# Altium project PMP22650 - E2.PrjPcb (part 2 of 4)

## Sheet PMP22650 PFC GaN PH2.SchDoc
size 431 x 279 mm; DocumentNumber: 6; SheetNumber: 6; SheetTotal: 16; PageSetup: Record=PageOptions¦CenterHorizontal=True¦CenterVertical=True¦PrintScale=0.69¦XCorrection=1.00¦YCorrection=1.00¦PrintKind=0¦BorderSize=5000000¦LeftOffset=0¦BottomOffset=0¦Orientation=2¦PaperLength=1000¦PaperWidth=1000¦Scale=100¦PaperSource=15¦PrintQuality=600¦MediaType=1¦DitherType=10¦PaperKind=Letter¦PrintScaleMode=1
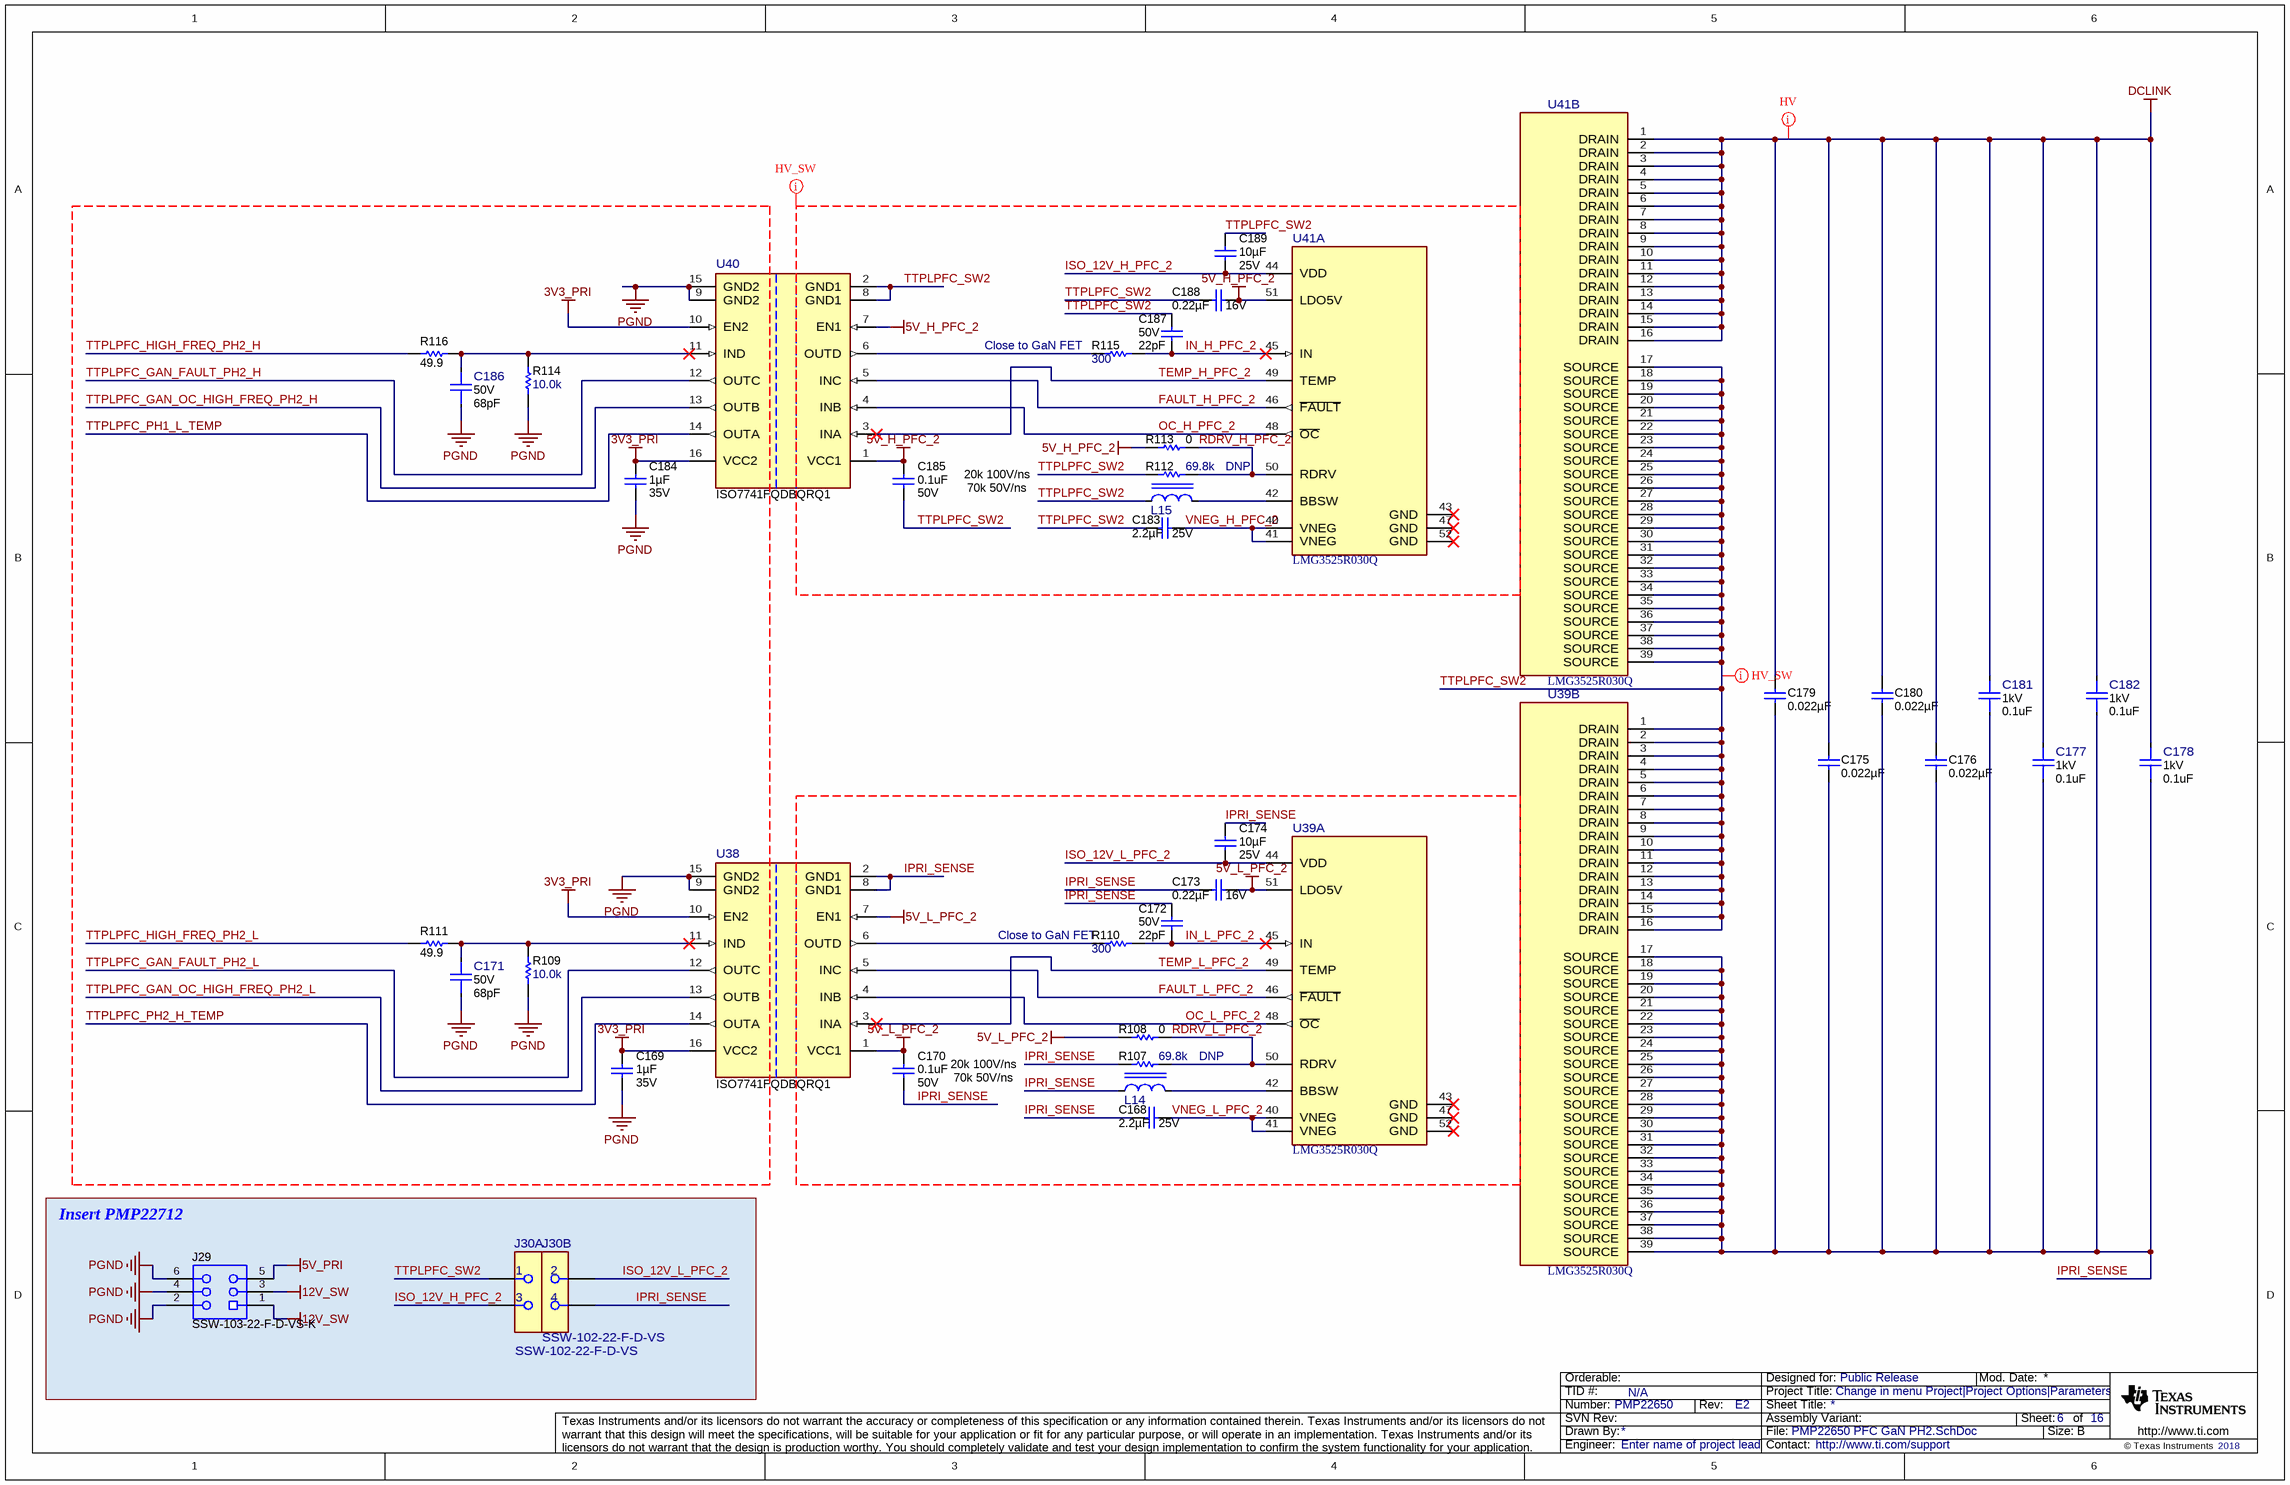
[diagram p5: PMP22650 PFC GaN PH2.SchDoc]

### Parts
C168  Cap_F: 2.2µF  VDC_V: 25V  [0805_HV]  (hidden comment: CGA4J3X7R1E225K125AB)
C169  VDC_V: 35V  ValueDisplayed: 1µF  [0402]  (hidden comment: GRT155R6YA105KE13D)
C170  VDC_V: 50V  ValueDisplayed: 0.1uF  [0402]  (hidden comment: GCM155R71H104KE02D)
C171  VDC_V: 50V  ValueDisplayed: 68pF  [FP-GCM1555C1H680JA16D_0402-MFG]  (hidden comment: GCM1555C1H680JA16D)
C172  VDC_V: 50V  ValueDisplayed: 22pF  [0402]  (hidden comment: GCM1555C1H220JA16D)
C173  VDC_V: 16V  ValueDisplayed: 0.22µF  [0402]  (hidden comment: GCM155R71C224KE02D)
C174  VDC_V: 25V  ValueDisplayed: 10µF  [1206_180]  (hidden comment: TMK316AB7106KLHT)
C175  ValueDisplayed: 0.022µF  [1206_190]  (hidden comment: C1206C223KDRACTU)
C176  ValueDisplayed: 0.022µF  [1206_190]  (hidden comment: C1206C223KDRACTU)
C177  VDC_V: 1kV  ValueDisplayed: 0.1uF  [FP-C1812X104KDRACAUTO_1812-MFG]  (hidden comment: C1812X104KDRACAUTO)
C178  VDC_V: 1kV  ValueDisplayed: 0.1uF  [FP-C1812X104KDRACAUTO_1812-MFG]  (hidden comment: C1812X104KDRACAUTO)
C179  ValueDisplayed: 0.022µF  [1206_190]  (hidden comment: C1206C223KDRACTU)
C180  ValueDisplayed: 0.022µF  [1206_190]  (hidden comment: C1206C223KDRACTU)
C181  VDC_V: 1kV  ValueDisplayed: 0.1uF  [FP-C1812X104KDRACAUTO_1812-MFG]  (hidden comment: C1812X104KDRACAUTO)
C182  VDC_V: 1kV  ValueDisplayed: 0.1uF  [FP-C1812X104KDRACAUTO_1812-MFG]  (hidden comment: C1812X104KDRACAUTO)
C183  Cap_F: 2.2µF  VDC_V: 25V  [0805_HV]  (hidden comment: CGA4J3X7R1E225K125AB)
C184  VDC_V: 35V  ValueDisplayed: 1µF  [0402]  (hidden comment: GRT155R6YA105KE13D)
C185  VDC_V: 50V  ValueDisplayed: 0.1uF  [0402]  (hidden comment: GCM155R71H104KE02D)
C186  VDC_V: 50V  ValueDisplayed: 68pF  [FP-GCM1555C1H680JA16D_0402-MFG]  (hidden comment: GCM1555C1H680JA16D)
C187  VDC_V: 50V  ValueDisplayed: 22pF  [0402]  (hidden comment: GCM1555C1H220JA16D)
C188  VDC_V: 16V  ValueDisplayed: 0.22µF  [0402]  (hidden comment: GCM155R71C224KE02D)
C189  VDC_V: 25V  ValueDisplayed: 10µF  [1206_180]  (hidden comment: TMK316AB7106KLHT)
J29  SSW-103-22-F-D-VS-K  [SAMTEC_SSW-103-22-F-D-VS-K]
J30  SSW-102-22-F-D-VS  [FP-SSW-102-22-F-D-VS_RCPT4-MFG]  (parts A,B of 2)
L14  MPIA2510V2-4R7-R  [FP-MPIA2510V2-4R7-R_1008-MFG]  (value not drawn)
L15  MPIA2510V2-4R7-R  [FP-MPIA2510V2-4R7-R_1008-MFG]  (value not drawn)
R107  ValueDisplayed: 69.8k  [0402]  (hidden comment: CRCW040269K8FKED)
R108  ValueDisplayed: 0  [0402]  (hidden comment: ERJ-2GE0R00X)
R109  ValueDisplayed: 10.0k  [0402]  (hidden comment: CRCW040210K0FKED)
R110  ValueDisplayed: 300  [0402]  (hidden comment: CRCW0402300RJNED)
R111  ValueDisplayed: 49.9  [0402]  (hidden comment: CRCW040249R9FKED)
R112  ValueDisplayed: 69.8k  [0402]  (hidden comment: CRCW040269K8FKED)
R113  ValueDisplayed: 0  [0402]  (hidden comment: ERJ-2GE0R00X)
R114  ValueDisplayed: 10.0k  [0402]  (hidden comment: CRCW040210K0FKED)
R115  ValueDisplayed: 300  [0402]  (hidden comment: CRCW0402300RJNED)
R116  ValueDisplayed: 49.9  [0402]  (hidden comment: CRCW040249R9FKED)
U38  ISO7741FQDBQRQ1  [DBQ0016A-MFG]
U39  LMG3525R030Q  [RQS0052A-MFG]  (parts A,B of 2)
U40  ISO7741FQDBQRQ1  [DBQ0016A-MFG]
U41  LMG3525R030Q  [RQS0052A-MFG]  (parts A,B of 2)

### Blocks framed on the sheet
Insert PMP22712: J29 J30

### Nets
3V3_PRI: C169.1 C184.1 U38.10(EN2) U38.16(VCC2) U40.10(EN2) U40.16(VCC2)
5V_H_PFC_2: C185.1 C188.1 R113.2 U40.1(VCC1) U40.7(EN1) U41.51(LDO5V)
5V_L_PFC_2: C170.1 C173.1 R108.2 U38.1(VCC1) U38.7(EN1) U39.51(LDO5V)
5V_PRI: J29.5
12V_SW: J29.1 J29.3
DCLINK: C175.1 C176.1 C177.2 C178.2 C179.1 C180.1 C181.2 C182.2 U41.1(DRAIN) U41.2(DRAIN) U41.3(DRAIN) U41.4(DRAIN) U41.5(DRAIN) U41.6(DRAIN) U41.7(DRAIN) U41.8(DRAIN) U41.9(DRAIN) U41.10(DRAIN) U41.11(DRAIN) U41.12(DRAIN) U41.13(DRAIN) U41.14(DRAIN) U41.15(DRAIN) U41.16(DRAIN)
PGND: C169.2 C171.1 C184.2 C186.1 J29.2 J29.4 J29.6 R109.1 R114.1 U38.9(GND2) U38.15(GND2) U40.9(GND2) U40.15(GND2)
FAULT_H_PFC_2: U40.5(INC) U41.46(~{FAULT})
FAULT_L_PFC_2: U38.5(INC) U39.46(~{FAULT})
IN_H_PFC_2: C187.2 R115.2 U41.45(IN)
IN_L_PFC_2: C172.2 R110.2 U39.45(IN)
IPRI_SENSE: C168.1 C170.2 C172.1 C173.2 C174.2 C175.2 C176.2 C177.1 C178.1 C179.2 C180.2 C181.1 C182.1 J30.4 L14.1 R107.1 U38.2(GND1) U38.8(GND1) U39.17(SOURCE) U39.18(SOURCE) U39.19(SOURCE) U39.20(SOURCE) U39.21(SOURCE) U39.22(SOURCE) U39.23(SOURCE) U39.24(SOURCE) U39.25(SOURCE) U39.26(SOURCE) U39.27(SOURCE) U39.28(SOURCE) U39.29(SOURCE) U39.30(SOURCE) U39.31(SOURCE) U39.32(SOURCE) U39.33(SOURCE) U39.34(SOURCE) U39.35(SOURCE) U39.36(SOURCE) U39.37(SOURCE) U39.38(SOURCE) U39.39(SOURCE)
ISO_12V_H_PFC_2: C189.1 J30.3 U41.44(VDD)
ISO_12V_L_PFC_2: C174.1 J30.2 U39.44(VDD)
OC_H_PFC_2: U40.4(INB) U41.48(~{OC})
OC_L_PFC_2: U38.4(INB) U39.48(~{OC})
RDRV_H_PFC_2: R112.2 R113.1 U41.50(RDRV)
RDRV_L_PFC_2: R107.2 R108.1 U39.50(RDRV)
TEMP_H_PFC_2: U40.3(INA) U41.49(TEMP)
TEMP_L_PFC_2: U38.3(INA) U39.49(TEMP)
TTPLPFC_GAN_FAULT_PH2_H: U40.12(OUTC)
TTPLPFC_GAN_FAULT_PH2_L: U38.12(OUTC)
TTPLPFC_GAN_OC_HIGH_FREQ_PH2_H: U40.13(OUTB)
TTPLPFC_GAN_OC_HIGH_FREQ_PH2_L: U38.13(OUTB)
TTPLPFC_HIGH_FREQ_PH2_H: R116.1
TTPLPFC_HIGH_FREQ_PH2_L: R111.1
TTPLPFC_PH1_L_TEMP: U40.14(OUTA)
TTPLPFC_PH2_H_TEMP: U38.14(OUTA)
TTPLPFC_SW2: C183.1 C185.2 C187.1 C188.2 C189.2 J30.1 L15.1 R112.1 U39.1(DRAIN) U39.2(DRAIN) U39.3(DRAIN) U39.4(DRAIN) U39.5(DRAIN) U39.6(DRAIN) U39.7(DRAIN) U39.8(DRAIN) U39.9(DRAIN) U39.10(DRAIN) U39.11(DRAIN) U39.12(DRAIN) U39.13(DRAIN) U39.14(DRAIN) U39.15(DRAIN) U39.16(DRAIN) U40.2(GND1) U40.8(GND1) U41.17(SOURCE) U41.18(SOURCE) U41.19(SOURCE) U41.20(SOURCE) U41.21(SOURCE) U41.22(SOURCE) U41.23(SOURCE) U41.24(SOURCE) U41.25(SOURCE) U41.26(SOURCE) U41.27(SOURCE) U41.28(SOURCE) U41.29(SOURCE) U41.30(SOURCE) U41.31(SOURCE) U41.32(SOURCE) U41.33(SOURCE) U41.34(SOURCE) U41.35(SOURCE) U41.36(SOURCE) U41.37(SOURCE) U41.38(SOURCE) U41.39(SOURCE)
VNEG_H_PFC_2: C183.2 U41.40(VNEG) U41.41(VNEG)
VNEG_L_PFC_2: C168.2 U39.40(VNEG) U39.41(VNEG)
NetC171_2: C171.2 R109.2 R111.2 U38.11(IND)
NetC186_2: C186.2 R114.2 R116.2 U40.11(IND)
NetL14_2: L14.2 U39.42(BBSW)
NetL15_2: L15.2 U41.42(BBSW)
NetR110_1: R110.1 U38.6(OUTD)
NetR115_1: R115.1 U40.6(OUTD)

Not connected (* = marked no-connect by the designer): U39 43(GND)* 47(GND)* 52(GND)*; U41 43(GND)* 47(GND)* 52(GND)*

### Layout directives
net class HV_SW: 5V_H_PFC_2, FAULT_H_PFC_2, IN_H_PFC_2, ISO_12V_H_PFC_2, OC_H_PFC_2, RDRV_H_PFC_2, TEMP_H_PFC_2, TTPLPFC_SW2, VNEG_H_PFC_2
net class HV: DCLINK

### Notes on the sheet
- (near R115) Close to GaN FET
- 20k 100V/ns
- 70k 50V/ns
- DNP
- (near R110) Close to GaN FET
- (near C170) 20k 100V/ns
- (near C170) 70k 50V/ns

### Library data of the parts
C168 C183 = CMP-0007975-2: CAP, CERM, 2.2 uF, 25 V, +/- 10%, X7R, AEC-Q200 Grade 1, 0805; Manufacturer: TDK; TaMin_C: -55°C; Polarized: N; SizeAreaWB_mm2: 6.75; Value1: Unknown; U/M: EA; Value: 2.2uF; TaMax_C: 125°C; SizeZ_mm: 1.45; SizeX_mm: 2; SizeY_mm: 1.25; Cap_Case: 0805; SizeArea_mm2: 2.5; AEC Qualified: Y; AEC Grade: 1; AEC Category: Q200
C169 C184 = CMP-0750099-1: CAP, CERM, 1 µF, 35 V,+/- 10%, X5R, AEC-Q200 Grade 3, 0402; Manufacturer: MuRata; AEC Grade: 3; AEC Category: Q200; Value: 1uF; SizeArea_mm2: 0.5; SizeZ_mm: 0.6; AEC Qualified: Y; TaMin_C: -55°C; SizeX_mm: 1; U/M: EA; Polarized: N; TaMax_C: 85°C
C170 C185 = CMP-0006356-2: CAP, CERM, 0.1 uF, 50 V, +/- 10%, X7R, AEC-Q200 Grade 1, 0402; Manufacturer: MuRata; TaMin_C: -55°C; Polarized: N; SizeAreaWB_mm2: 3; Value1: Unknown; U/M: EA; Value: 0.1uF; TaMax_C: 125°C; SizeZ_mm: 0.6; SizeX_mm: 1; SizeY_mm: 0.5; AEC Qualified: Y; Cap_F: 100nF; AEC Category: Q200
C171 C186 = CMP-0090521-1: 68pF ±5% 50V Ceramic Capacitor C0G, NP0 0402 (1005 Metric); Manufacturer: Murata; AEC Qualified: Yes; AEC Grade: Grade 1; TempCo: 30ppm/°C; SizeZ_mm: 0.55mm
C172 C187 = CMP-0006348-2: CAP, CERM, 22 pF, 50 V, +/- 5%, C0G/NP0, AEC-Q200 Grade 1, 0402; Manufacturer: MuRata; TaMin_C: -55°C; Polarized: N; SizeAreaWB_mm2: 3; Value1: Unknown; U/M: EA; Value: 22pF; TaMax_C: 125°C; SizeZ_mm: 0.6; SizeX_mm: 1; SizeY_mm: 0.5; AEC Qualified: Y; AEC Category: Q200
C173 C188 = CMP-0078265-1: CAP, CERM, 0.22 µF, 16 V,+/- 10%, X7R, AEC-Q200 Grade 1, 0402; Manufacturer: MuRata; TaMin_C: -55°C; Polarized: N; SizeAreaWB_mm2: 3; U/M: EA; Value: 0.22uF; TaMax_C: 125°C; SizeZ_mm: 0.6; SizeX_mm: 1; SizeY_mm: 0.5; AEC Qualified: Y; Cap_F: 220nF; AEC Category: Q200
C174 C189 = CMP-0750154-1: CAP, CERM, 10 µF, 25 V,+/- 10%, X7R, AEC-Q200 Grade 1, 1206; Manufacturer: Taiyo Yuden; AEC Qualified: Y; SizeZ_mm: 1.8; TaMax_C: 125°C; TaMin_C: -55°C; Cap_Case: 1206; Polarized: N; AEC Grade: 1; SizeY_mm: 1.6; Value: 10uF; SizeX_mm: 3.2; SizeAreaWB_mm2: 10.92; AEC Category: Q200; U/M: EA; SizeArea_mm2: 5.12
C175 C176 C179 C180 = CMP-0084048-1: CAP, CERM, 0.022 µF, 1000 V,+/- 10%, X7R, AEC-Q200 Grade 1, 1206; Manufacturer: Kemet; Polarized: N; CompType: Capacitor; Value: 0.022uF; U/M: EA; Cap_F: 22nF; VDC_V: 1kV; Value2: 1000V; TaMin_C: -55°C; TaMax_C: 125°C; Cap_Case: 1206; SizeArea_mm2: 5.12; SizeAreaWB_mm2: 10.92; SizeX_mm: 3.2; SizeY_mm: 1.6; SizeZ_mm: 1.9; AEC Category: Q200; AEC Qualified: Y; AEC Grade: 1
C177 C178 C181 C182 = CMP-0090548-1: 0.1µF ±10% 1000V (1kV) Ceramic Capacitor X7R 1812 (4532 Metric); Manufacturer: Kemet; SizeZ_mm: 1.85mm; AEC Qualified: Yes; Cap_F: 100nF; TempCo: 15%; Value: 100nF; AEC Grade: Grade 1
J29 = CMP-0055666-1: Receptacle, 2.54mm, 3x2, Tin, SMT; Manufacturer: Samtec; CNHeader: FALSE; Current_A: 5.7A; Gender: Female; CompType: Socket Strip; Row_Count: 2; RowSpacing_mm: 2.54; ContactFinish: Gold; CT: TRUE; Cert_UL: Y
J30 = CMP-0090790-1: 4 Position Receptacle Connector  Surface Mount; Manufacturer: Samtec; DUT-Pitch_mm: 2.54mm; SizeZ_mm: 10.21mm; Current_A: 4.7A; ContactFinish: Gold,Nickel; Conn Gender: Female; Voltage_V: 655V; Is Female: yes; AEC Qualified: No; Row_Count: 2; Conn Orientation: Vertical; Standoff Height: 0.97mm
L14 L15 = CMP-0090507-1: 4.7µH Shielded Molded Inductor 1.22A 262mOhm Max 1008 (2520 Metric); Manufacturer: Eaton; Material: Metal Composite; Value: 4.7uH; Test Frequency: 1MHz; Isat: 1.8A; DCR_ohm: 0.262; AEC Grade: Grade 1; Tolerance_%: 20%; AEC Qualified: Yes; Self Resonant Frequency: 25MHz; SizeZ_mm: 1.05mm; Shrouded: true
R107 R112 = CMP-0026510-2: RES, 69.8 k, 1%, 0.063 W, AEC-Q200 Grade 0, 0402; Manufacturer: Vishay-Dale; Power_W: 63mW; TempCo: 100 ppm/C; Value_Code: 69k8; Value: 69.8k; EIA_Code: E96; SizeX_mm: 1; SizeY_mm: 0.5; SizeZ_mm: 0.6; Value2: 0.063W; AEC Qualified: Y; VDC_V: 50V; AEC Category: Q200; AEC Grade: 0
R108 R113 = CMP-0026992-3: RES, 0, 5%, 0.1 W, AEC-Q200 Grade 0, 0402; Manufacturer: Panasonic; Power_W: 100mW; TempCo: 600 ppm/C; Value_Code: 0000; Value: 0; EIA_Code: E24; SizeX_mm: 1; SizeY_mm: 0.5; SizeZ_mm: 0.6; Value2: 0.1W; AEC Qualified: Y; VDC_V: 50V; AEC Category: Q200; SizeAreaWB_mm2: 3
R109 R114 = CMP-0025958-3: RES, 10.0 k, 1%, 0.063 W, AEC-Q200 Grade 0, 0402; Manufacturer: Vishay-Dale; Power_W: 63mW; TempCo: 100 ppm/C; Value_Code: 10k0; Value: 10.0k; EIA_Code: E96; Res_ohm: 10k; SizeX_mm: 1; SizeY_mm: 0.5; SizeZ_mm: 0.6; Value2: 0.063W; AEC Qualified: Y; VDC_V: 50V; AEC Category: Q200; AEC Grade: 0
R110 R115 = CMP-0026902-3: RES, 300, 5%, 0.063 W, AEC-Q200 Grade 0, 0402; Manufacturer: Vishay-Dale; Power_W: 63mW; TempCo: 200 ppm/C; Value_Code: 300R; Value: 300; EIA_Code: E24; SizeX_mm: 1; SizeY_mm: 0.5; SizeZ_mm: 0.6; Value2: 0.063W; AEC Qualified: Y; VDC_V: 50V; AEC Category: Q200; AEC Grade: 0
R111 R116 = CMP-0026404-2: RES, 49.9, 1%, 0.063 W, AEC-Q200 Grade 0, 0402; Manufacturer: Vishay-Dale; Power_W: 63mW; TempCo: 100 ppm/C; Value_Code: 49R9; Value: 49.9; EIA_Code: E96; SizeX_mm: 1; SizeY_mm: 0.5; SizeZ_mm: 0.6; Value2: 0.063W; AEC Qualified: Y; VDC_V: 50V; AEC Category: Q200; AEC Grade: 0
U38 U40 = CMP-0090469-1: Manufacturer: Texas Instruments; TaMin_C: -40°C; TaMax_C: +125°C; TJmax_C: +150°C; AEC Grade: Grade 1; Min Supply Voltage: 2.25V; AEC Qualified: Yes; Max Supply Voltage: 5.5V; Standoff Height: 0.11mm; Nominal Supply Current: 1.5-18mA; SizeZ_mm: 1.75mm
U39 U41 = CMP-0089968-2: 650-V 30-mΩ GaN FET with Integrated Driver and Protection; Manufacturer: Texas Instruments; Output Voltage: 520V; Nominal Supply Current: 540uA; Min Supply Voltage: 7.5V; Standoff Height: 0mm; AEC Grade: Grade 1; Max Supply Voltage: 18V; Number Of Outputs: 1; AEC Qualified: Yes; TJmax_C: +125°C; SizeZ_mm: 1mm; AEC Category: Q200; CompType: IC

## Sheet PMP22650 PFC LF FET Gate Driver.SchDoc
size A4; Date: Not shown in title block; ApprovedBy: Not shown in title block; CheckedBy: Not shown in title block; Author: Not shown in title block; CompanyName: Not shown in title block; Engineer: Not shown in title block; Organization: Not shown in title block; Address1: Not shown in title block; Address2: Not shown in title block; Address3: Not shown in title block; Address4: Not shown in title block; DocumentNumber: 7; Revision: Use project parameter SCH_Rev; SheetNumber: 7; SheetTotal: 16; PageSetup: Record=PageOptions¦CenterHorizontal=True¦CenterVertical=True¦PrintScale=1.00¦XCorrection=1.00¦YCorrection=1.00¦PrintKind=0¦BorderSize=5000000¦LeftOffset=0¦BottomOffset=0¦Orientation=2¦PaperLength=1000¦PaperWidth=1000¦Scale=100¦PaperSource=15¦PrintQuality=600¦MediaType=1¦DitherType=10¦PaperKind=Letter¦PrintScaleMode=1
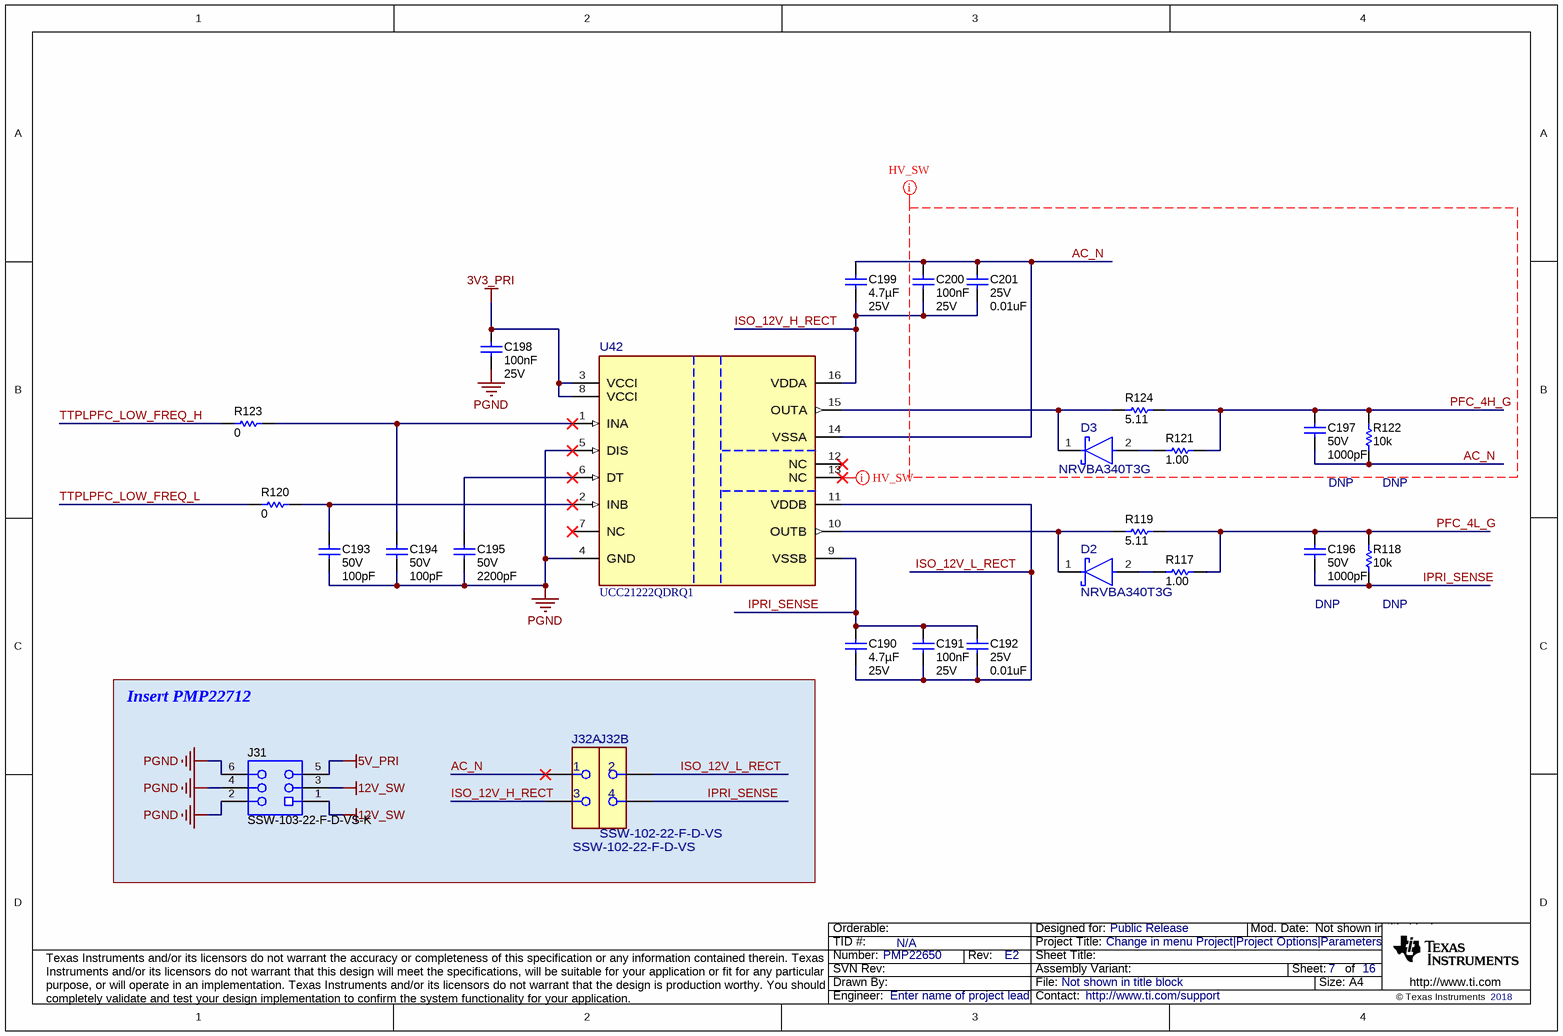
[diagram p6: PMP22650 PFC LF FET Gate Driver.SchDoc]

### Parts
C190  Cap_F: 4.7µF  VDC_V: 25V  [0805L]  (hidden comment: CGA4J1X7R1E475K125AC)
C191  Cap_F: 100nF  VDC_V: 25V  [0603]  (hidden comment: CGA3E2X7R1E104K080AA)
C192  VDC_V: 25V  ValueDisplayed: 0.01uF  [0603]  (hidden comment: C0603C103J3GECAUTO)
C193  VDC_V: 50V  ValueDisplayed: 100pF  [0603]  (hidden comment: CGA3E2NP01H101J080AA)
C194  VDC_V: 50V  ValueDisplayed: 100pF  [0603]  (hidden comment: CGA3E2NP01H101J080AA)
C195  VDC_V: 50V  ValueDisplayed: 2200pF  [0402]  (hidden comment: CGA2B2X7R1H222K050BA)
C196  VDC_V: 50V  ValueDisplayed: 1000pF  [0402]  (hidden comment: CGA2B2X7R1H102K050BA)
C197  VDC_V: 50V  ValueDisplayed: 1000pF  [0402]  (hidden comment: CGA2B2X7R1H102K050BA)
C198  Cap_F: 100nF  VDC_V: 25V  [0603]  (hidden comment: CGA3E2X7R1E104K080AA)
C199  Cap_F: 4.7µF  VDC_V: 25V  [0805L]  (hidden comment: CGA4J1X7R1E475K125AC)
C200  Cap_F: 100nF  VDC_V: 25V  [0603]  (hidden comment: CGA3E2X7R1E104K080AA)
C201  VDC_V: 25V  ValueDisplayed: 0.01uF  [0603]  (hidden comment: C0603C103J3GECAUTO)
D2  NRVBA340T3G  [FP-NRVBA340T3G_SMA-MFG]
D3  NRVBA340T3G  [FP-NRVBA340T3G_SMA-MFG]
J31  SSW-103-22-F-D-VS-K  [SAMTEC_SSW-103-22-F-D-VS-K]
J32  SSW-102-22-F-D-VS  [FP-SSW-102-22-F-D-VS_RCPT4-MFG]  (parts A,B of 2)
R117  ValueDisplayed: 1.00  [1206]  (hidden comment: CRCW12061R00FKEA)
R118  ValueDisplayed: 10k  [0603]  (hidden comment: CRCW060310K0JNEA)
R119  ValueDisplayed: 5.11  [1206]  (hidden comment: CRCW12065R11FKEA)
R120  ValueDisplayed: 0  [0402]  (hidden comment: RK73Z1ETTP)
R121  ValueDisplayed: 1.00  [1206]  (hidden comment: CRCW12061R00FKEA)
R122  ValueDisplayed: 10k  [0603]  (hidden comment: CRCW060310K0JNEA)
R123  ValueDisplayed: 0  [0402]  (hidden comment: RK73Z1ETTP)
R124  ValueDisplayed: 5.11  [1206]  (hidden comment: CRCW12065R11FKEA)
U42  UCC21222QDRQ1  [D0016B-MFG]

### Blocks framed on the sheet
Insert PMP22712: J31 J32

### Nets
3V3_PRI: C198.1 U42.3(VCCI) U42.8(VCCI)
5V_PRI: J31.5
12V_SW: J31.1 J31.3
PGND: C193.2 C194.2 C195.2 C198.2 J31.2 J31.4 J31.6 U42.4(GND) U42.5(DIS)
AC_N: C197.2 C199.1 C200.1 C201.1 J32.1 R122.1 U42.14(VSSA)
IPRI_SENSE: C190.1 C191.1 C192.1 C196.2 J32.4 R118.1 U42.9(VSSB)
ISO_12V_H_RECT: C199.2 C200.2 C201.2 J32.3 U42.16(VDDA)
ISO_12V_L_RECT: C190.2 C191.2 C192.2 J32.2 U42.11(VDDB)
PFC_4H_G: C197.1 R121.2 R122.2 R124.2
PFC_4L_G: C196.1 R117.2 R118.2 R119.2
TTPLPFC_LOW_FREQ_H: R123.1
TTPLPFC_LOW_FREQ_L: R120.1
NetC193_1: C193.1 R120.2 U42.2(INB)
NetC194_1: C194.1 R123.2 U42.1(INA)
NetC195_1: C195.1 U42.6(DT)
NetD2_1: D2.1(Cathode) R119.1 U42.10(OUTB)
NetD2_2: D2.2(Anode) R117.1
NetD3_1: D3.1(Cathode) R124.1 U42.15(OUTA)
NetD3_2: D3.2(Anode) R121.1

Not connected (* = marked no-connect by the designer): U42 7(NC)* 12(NC)* 13(NC)*

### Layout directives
net class HV: AC_N, NetU42_13, PFC_4H_G

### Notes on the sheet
- DNP
- (near R122) DNP
- (near R118) DNP

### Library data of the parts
C190 C199 = CMP-0076706-1: CAP, CERM, 4.7 µF, 25 V,+/- 10%, X7R, AEC-Q200 Grade 1, 0805; Manufacturer: TDK; SizeAreaWB_mm2: 6.75; SizeArea_mm2: 2.5; AEC Qualified: Y; AEC Category: Q200; Value: 4.7uF; TaMax_C: 125°C; SizeZ_mm: 1.45; AEC Grade: 1; Polarized: N; TaMin_C: -55°C; SizeY_mm: 1.25; U/M: EA; SizeX_mm: 2.0; Cap_Case: 2x1.25x1.25mm
C191 C198 C200 = CMP-0007077-5: CAP, CERM, 0.1 uF, 25 V, +/- 10%, X7R, AEC-Q200 Grade 1, 0603; Manufacturer: TDK; TaMin_C: -55°C; Polarized: N; SizeAreaWB_mm2: 4.68; Value1: Unknown; U/M: EA; Value: 0.1uF; TaMax_C: 125°C; SizeZ_mm: 1; SizeX_mm: 1.6; SizeY_mm: 0.8; SizeArea_mm2: 1.28; AEC Qualified: Y; AEC Category: Q200
C192 C201 = CMP-0006849-4: CAP, CERM, 0.01 uF, 25 V, +/- 5%, C0G/NP0, AEC-Q200 Grade 1, 0603; Manufacturer: Kemet; TaMin_C: -55°C; Polarized: N; SizeAreaWB_mm2: 4.68; Value1: Unknown; U/M: EA; Value: 0.01uF; TaMax_C: 125°C; SizeZ_mm: 1; SizeX_mm: 1.6; SizeY_mm: 0.8; SizeArea_mm2: 1.28; AEC Qualified: Y; Cap_F: 10nF; AEC Category: Q200
C193 C194 = CMP-0007075-4: CAP, CERM, 100 pF, 50 V, +/- 5%, C0G/NP0, AEC-Q200 Grade 0, 0603; Manufacturer: TDK; TaMin_C: -55°C; Polarized: N; SizeAreaWB_mm2: 4.68; Value1: Unknown; U/M: EA; Value: 100pF; TaMax_C: 150°C; SizeZ_mm: 1; SizeX_mm: 1.6; SizeY_mm: 0.8; SizeArea_mm2: 1.28; AEC Qualified: Y; AEC Grade: 0; AEC Category: Q200
C195 = CMP-0006317-2: CAP, CERM, 2200 pF, 50 V, +/- 10%, X7R, AEC-Q200 Grade 1, 0402; Manufacturer: TDK; TaMin_C: -55°C; ESR_ohm: 1.07794; Polarized: N; SizeAreaWB_mm2: 3; Value1: 1.07794 ohm; U/M: EA; Value: 2200pF; TaMax_C: 125°C; SizeZ_mm: 0.6; SizeX_mm: 1; SizeY_mm: 0.5; AEC Qualified: Y; Cap_F: 2.2nF; IRMS_A: 264.071mA; AEC Category: Q200
C196 C197 = CMP-0006314-2: CAP, CERM, 1000 pF, 50 V, +/- 10%, X7R, AEC-Q200 Grade 1, 0402; Manufacturer: TDK; TaMin_C: -55°C; ESR_ohm: 2.25564; Polarized: N; SizeAreaWB_mm2: 3; Value1: 2.25564 ohm; U/M: EA; Value: 1000pF; TaMax_C: 125°C; SizeZ_mm: 0.6; SizeX_mm: 1; SizeY_mm: 0.5; AEC Qualified: Y; Cap_F: 1nF; IRMS_A: 280.466mA; AEC Category: Q200
D2 D3 = CMP-0090591-1: Diode Schottky 40V 3A Surface Mount SMA; Manufacturer: ON Semiconductor; TJmax_C: 150°C; Peak Reverse Current: 0.3mA; Import Ts: 1521842727; Ciiva Ids: 822566; Max Surge Forward Current: 100A; AEC Qualified: Yes; SizeZ_mm: 2.2mm; AEC Grade: Grade 0; Standoff Height: 0.05mm
J31 = CMP-0055666-1: as J29 on sheet PMP22650 PFC GaN PH2
J32 = CMP-0090790-1: as J30 on sheet PMP22650 PFC GaN PH2
R117 R121 = CMP-0016745-3: RES, 1.00, 1%, 0.25 W, AEC-Q200 Grade 0, 1206; Manufacturer: Vishay-Dale; Power_W: 250mW; TempCo: 100 ppm/C; Value_Code: 1R00; Value: 1.00; EIA_Code: E96; Res_ohm: 1; SizeX_mm: 3.2; SizeY_mm: 1.6; SizeZ_mm: 1.35; Value2: 0.25W; SizeArea_mm2: 5.12; AEC Qualified: Y; VDC_V: 200V; AEC Category: Q200; AEC Grade: 0
R118 R122 = CMP-0025701-4: RES, 10 k, 5%, 0.1 W, AEC-Q200 Grade 0, 0603; Manufacturer: Vishay-Dale; Power_W: 100mW; TempCo: 200 ppm/C; Value_Code: 10k0; Value: 10k; EIA_Code: E24; SizeX_mm: 1.6; SizeY_mm: 0.8; SizeZ_mm: 1; Value2: 0.1W; SizeArea_mm2: 1.28; AEC Qualified: Y; VDC_V: 75V; AEC Category: Q200; AEC Grade: 0
R119 R124 = CMP-0017092-3: RES, 5.11, 1%, 0.25 W, AEC-Q200 Grade 0, 1206; Manufacturer: Vishay-Dale; Power_W: 250mW; TempCo: 100 ppm/C; Value_Code: 5R11; Value: 5.11; EIA_Code: E96; SizeX_mm: 3.2; SizeY_mm: 1.6; SizeZ_mm: 1.35; Value2: 0.25W; SizeArea_mm2: 5.12; AEC Qualified: Y; VDC_V: 200V; AEC Category: Q200; AEC Grade: 0
R120 R123 = CMP-0027007-2: RES, 0, 5%, 0.063 W, AEC-Q200 Grade 0, 0402; Manufacturer: KOA Speer; Power_W: 63mW; TempCo: ppm/C; Value_Code: 0000; U/M: EA; Value: 0; EIA_Code: E24; SizeX_mm: 1; SizeY_mm: 0.5; SizeZ_mm: 0.6; Value2: 0.063W; AEC Qualified: Y; AEC Category: Q200
U42 = CMP-0090594-2: Half-Bridge Gate Driver IC CMOS/TTL 16-SOIC; Manufacturer: Texas Instruments; TaMin_C: -40°C; AEC Category: Q200; Turn On Delay Time: 28ns; Nominal Supply Current: 1-2.5mA; Max Power Dissipation: 1825mW; TJmax_C: +150°C; SizeZ_mm: 1.75mm; TaMax_C: +125°C; Fall Time: 6ns; Output Voltage: 9.2-18V; Standoff Height: 0.1mm; AEC Qualified: Yes; Rise Time: 5ns; Max Supply Voltage: 5.5V; Number Of Outputs: 2; AEC Grade: Grade 1; Propagation Delay: 25ns; Min Supply Voltage: 3V

## Sheet PMP22650 Control.schdoc
size 431 x 279 mm; Date: Not shown in title block; ApprovedBy: Not shown in title block; CheckedBy: Not shown in title block; Author: Not shown in title block; CompanyName: Not shown in title block; Engineer: Not shown in title block; Organization: Not shown in title block; Address1: Not shown in title block; Address2: Not shown in title block; Address3: Not shown in title block; Address4: Not shown in title block; DocumentNumber: 8; Revision: Use project parameter SCH_Rev; SheetNumber: 8; SheetTotal: 16; PageSetup: Record=PageOptions¦CenterHorizontal=True¦CenterVertical=True¦PrintScale=1.00¦XCorrection=1.00¦YCorrection=1.00¦PrintKind=0¦BorderSize=5000000¦LeftOffset=0¦BottomOffset=0¦Orientation=2¦PaperLength=1000¦PaperWidth=1000¦Scale=100¦PaperSource=15¦PrintQuality=600¦MediaType=1¦DitherType=10¦PaperKind=Letter¦PrintScaleMode=1
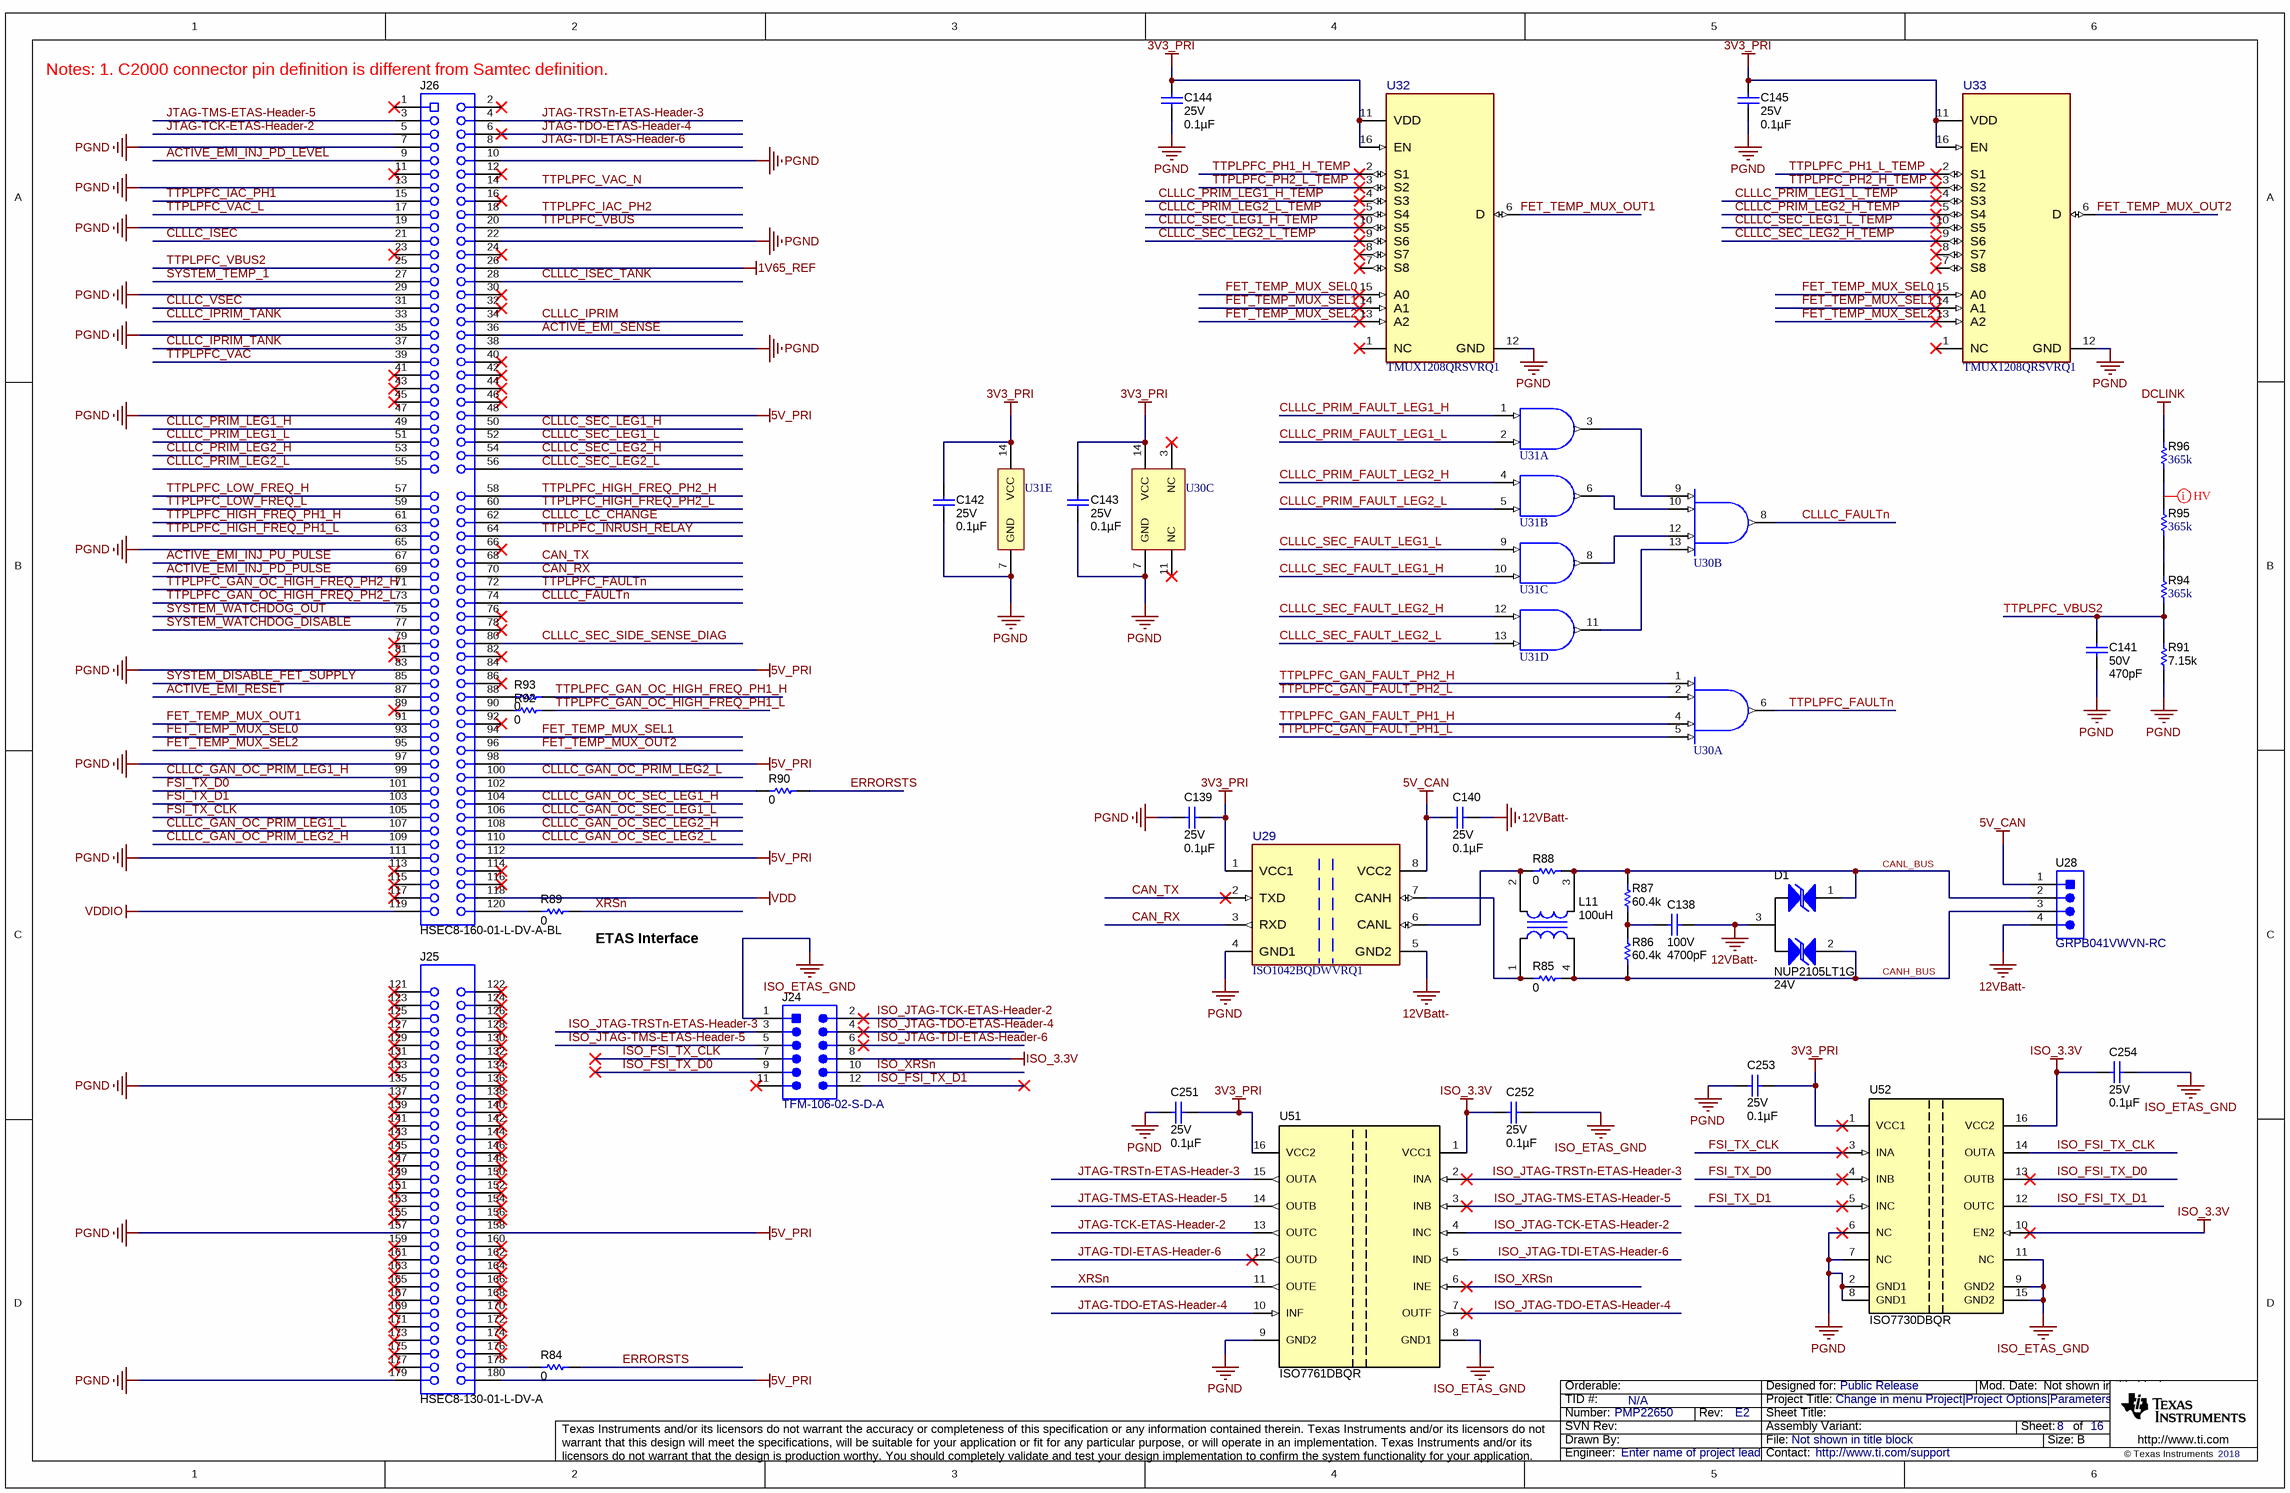
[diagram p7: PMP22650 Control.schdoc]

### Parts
C138  VDC_V: 100V  ValueDisplayed: 4700pF  [0603]  (hidden comment: CGA3E2X7R2A472K080AA)
C139  VDC_V: 25V  ValueDisplayed: 0.1µF  [0402]  (hidden comment: CGA2B3X7R1E104K050BB)
C140  VDC_V: 25V  ValueDisplayed: 0.1µF  [0402]  (hidden comment: CGA2B3X7R1E104K050BB)
C141  VDC_V: 50V  ValueDisplayed: 470pF  [0603]  (hidden comment: GCM1885C1H471JA16D)
C142  VDC_V: 25V  ValueDisplayed: 0.1µF  [0402]  (hidden comment: CGA2B3X7R1E104K050BB)
C143  VDC_V: 25V  ValueDisplayed: 0.1µF  [0402]  (hidden comment: CGA2B3X7R1E104K050BB)
C144  VDC_V: 25V  ValueDisplayed: 0.1µF  [0402]  (hidden comment: CGA2B3X7R1E104K050BB)
C145  VDC_V: 25V  ValueDisplayed: 0.1µF  [0402]  (hidden comment: CGA2B3X7R1E104K050BB)
C251  VDC_V: 25V  ValueDisplayed: 0.1µF  [0402]  (hidden comment: CGA2B3X7R1E104K050BB)
C252  VDC_V: 25V  ValueDisplayed: 0.1µF  [0402]  (hidden comment: CGA2B3X7R1E104K050BB)
C253  VDC_V: 25V  ValueDisplayed: 0.1µF  [0402]  (hidden comment: CGA2B3X7R1E104K050BB)
C254  VDC_V: 25V  ValueDisplayed: 0.1µF  [0402]  (hidden comment: CGA2B3X7R1E104K050BB)
D1  NUP2105LT1G  value 24V  [SOT-23]
J24  TFM-106-02-S-D-A  [Samtec_TFM-106-02-x-D-A]
J25  HSEC8-130-01-L-DV-A  [controlCARD-180HSEC-60pinAddon]
J26  HSEC8-160-01-L-DV-A-BL  [controlCARD-120HSEC]
L11  ValueDisplayed: 100uH  [ACT45B]  (hidden comment: ACT45B-101-2P-TL003)
R84  ValueDisplayed: 0  [0603]  (hidden comment: ERJ-3GEY0R00V)
R85  ValueDisplayed: 0  [0603]  (hidden comment: RMCF0603ZT0R00)
R86  ValueDisplayed: 60.4k  [0603]  (hidden comment: CRCW060360K4FKEA)
R87  ValueDisplayed: 60.4k  [0603]  (hidden comment: CRCW060360K4FKEA)
R88  ValueDisplayed: 0  [0603]  (hidden comment: RMCF0603ZT0R00)
R89  ValueDisplayed: 0  [0603]  (hidden comment: ERJ-3GEY0R00V)
R90  ValueDisplayed: 0  [0603]  (hidden comment: ERJ-3GEY0R00V)
R91  ValueDisplayed: 7.15k  [0603]  (hidden comment: CRCW06037K15FKEA)
R92  ValueDisplayed: 0  [0603]  (hidden comment: ERJ-3GEY0R00V)
R93  ValueDisplayed: 0  [0603]  (hidden comment: ERJ-3GEY0R00V)
R94  ValueDisplayed: 365k  [1206]  (hidden comment: CRCW1206365KFKEA)
R95  ValueDisplayed: 365k  [1206]  (hidden comment: CRCW1206365KFKEA)
R96  ValueDisplayed: 365k  [1206]  (hidden comment: CRCW1206365KFKEA)
U28  GRPB041VWVN-RC  [Sullins_GRPB041VWVN-RC]
U29  ISO1042BQDWVRQ1  [DWV0008A-MFG]
U30  SN74HC21QPWRG4Q1  [PW0014A_N]  (value not drawn)  (parts A,B,C of 3)
U31  SN74AHCT08QPWRG4Q1  [PW0014A_N]  (value not drawn)  (parts A,B,C,D,E of 5)
U32  TMUX1208QRSVRQ1  [RSV0016A-MFG]
U33  TMUX1208QRSVRQ1  [RSV0016A-MFG]
U51  ISO7761DBQR  [DBQ0016A_N]
U52  ISO7730DBQR  [DBQ0016A_N]

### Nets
1V65_REF: J26.26
3V3_PRI: C139.1 C142.1 C143.1 C144.2 C145.2 C251.1 C253.1 U29.1(VCC1) U30.14(VCC) U31.14(VCC) U32.11(VDD) U32.16(EN) U33.11(VDD) U33.16(EN) U51.16(VCC2) U52.1(VCC1)
5V_CAN: C140.1 U28.1 U29.8(VCC2)
5V_PRI: J25.158 J25.180 J26.48 J26.84 J26.98 J26.112
12VBatt-: C138.1 C140.2 D1.3 U28.4 U29.5(GND2)
DCLINK: R96.1
ISO_3.3V: C252.2 C254.2 J24.8 U51.1(VCC1) U52.10(EN2) U52.16(VCC2)
ISO_ETAS_GND: C252.1 C254.1 J24.1 U51.8(GND1) U52.9(GND2) U52.11(NC) U52.15(GND2)
PGND: C139.2 C141.2 C142.2 C143.2 C144.1 C145.1 C251.2 C253.2 J25.135 J25.157 J25.179 J26.7 J26.10 J26.13 J26.19 J26.22 J26.29 J26.35 J26.38 J26.47 J26.65 J26.83 J26.97 J26.111 R91.2 U29.4(GND1) U30.7(GND) U31.7(GND) U32.12(GND) U33.12(GND) U51.9(GND2) U52.2(GND1) U52.6(NC) U52.7(NC) U52.8(GND1)
VDD: J26.118
VDDIO: J26.119
ACTIVE_EMI_INJ_PD_LEVEL: J26.9
ACTIVE_EMI_INJ_PD_PULSE: J26.69
ACTIVE_EMI_INJ_PU_PULSE: J26.67
ACTIVE_EMI_RESET: J26.87
ACTIVE_EMI_SENSE: J26.36
CAN_RX: J26.70 U29.3(RXD)
CAN_TX: J26.68 U29.2(TXD)
CANH_BUS: D1.2 L11.4 R85.2 R86.1 U28.3
CANL_BUS: D1.1 L11.3 R87.2 R88.2 U28.2
CLLLC_FAULTn: J26.74 U30.8(2Y)
CLLLC_GAN_OC_PRIM_LEG1_H: J26.99
CLLLC_GAN_OC_PRIM_LEG1_L: J26.107
CLLLC_GAN_OC_PRIM_LEG2_H: J26.109
CLLLC_GAN_OC_PRIM_LEG2_L: J26.100
CLLLC_GAN_OC_SEC_LEG1_H: J26.104
CLLLC_GAN_OC_SEC_LEG1_L: J26.106
CLLLC_GAN_OC_SEC_LEG2_H: J26.108
CLLLC_GAN_OC_SEC_LEG2_L: J26.110
CLLLC_IPRIM: J26.34
CLLLC_IPRIM_TANK: J26.33 J26.37
CLLLC_ISEC: J26.21
CLLLC_ISEC_TANK: J26.28
CLLLC_LC_CHANGE: J26.62
CLLLC_PRIM_FAULT_LEG1_H: U31.1(1A)
CLLLC_PRIM_FAULT_LEG1_L: U31.2(1B)
CLLLC_PRIM_FAULT_LEG2_H: U31.4(2A)
CLLLC_PRIM_FAULT_LEG2_L: U31.5(2B)
CLLLC_PRIM_LEG1_H: J26.49
CLLLC_PRIM_LEG1_H_TEMP: U32.4(S3)
CLLLC_PRIM_LEG1_L: J26.51
CLLLC_PRIM_LEG1_L_TEMP: U33.4(S3)
CLLLC_PRIM_LEG2_H: J26.53
CLLLC_PRIM_LEG2_H_TEMP: U33.5(S4)
CLLLC_PRIM_LEG2_L: J26.55
CLLLC_PRIM_LEG2_L_TEMP: U32.5(S4)
CLLLC_SEC_FAULT_LEG1_H: U31.10(3B)
CLLLC_SEC_FAULT_LEG1_L: U31.9(3A)
CLLLC_SEC_FAULT_LEG2_H: U31.12(4A)
CLLLC_SEC_FAULT_LEG2_L: U31.13(4B)
CLLLC_SEC_LEG1_H: J26.50
CLLLC_SEC_LEG1_H_TEMP: U32.10(S5)
CLLLC_SEC_LEG1_L: J26.52
CLLLC_SEC_LEG1_L_TEMP: U33.10(S5)
CLLLC_SEC_LEG2_H: J26.54
CLLLC_SEC_LEG2_H_TEMP: U33.9(S6)
CLLLC_SEC_LEG2_L: J26.56
CLLLC_SEC_LEG2_L_TEMP: U32.9(S6)
CLLLC_SEC_SIDE_SENSE_DIAG: J26.80
CLLLC_VSEC: J26.31
ERRORSTS: R84.2 R90.2
FET_TEMP_MUX_OUT1: J26.91 U32.6(D)
FET_TEMP_MUX_OUT2: J26.96 U33.6(D)
FET_TEMP_MUX_SEL0: J26.93 U32.15(A0) U33.15(A0)
FET_TEMP_MUX_SEL1: J26.94 U32.14(A1) U33.14(A1)
FET_TEMP_MUX_SEL2: J26.95 U32.13(A2) U33.13(A2)
FSI_TX_CLK: J26.105 U52.3(INA)
FSI_TX_D0: J26.101 U52.4(INB)
FSI_TX_D1: J26.103 U52.5(INC)
ISO_FSI_TX_CLK: J24.7 U52.14(OUTA)
ISO_FSI_TX_D0: J24.9 U52.13(OUTB)
ISO_FSI_TX_D1: J24.12 U52.12(OUTC)
ISO_JTAG-TCK-ETAS-Header-2: J24.2 U51.4(INC)
ISO_JTAG-TDI-ETAS-Header-6: J24.6 U51.5(IND)
ISO_JTAG-TDO-ETAS-Header-4: J24.4 U51.7(OUTF)
ISO_JTAG-TMS-ETAS-Header-5: J24.5 U51.3(INB)
ISO_JTAG-TRSTn-ETAS-Header-3: J24.3 U51.2(INA)
ISO_XRSn: J24.10 U51.6(INE)
JTAG-TCK-ETAS-Header-2: J26.5 U51.13(OUTC)
JTAG-TDI-ETAS-Header-6: J26.8 U51.12(OUTD)
JTAG-TDO-ETAS-Header-4: J26.6 U51.10(INF)
JTAG-TMS-ETAS-Header-5: J26.3 U51.14(OUTB)
JTAG-TRSTn-ETAS-Header-3: J26.4 U51.15(OUTA)
SYSTEM_DISABLE_FET_SUPPLY: J26.85
SYSTEM_TEMP_1: J26.27
SYSTEM_WATCHDOG_DISABLE: J26.77
SYSTEM_WATCHDOG_OUT: J26.75
TTPLPFC_FAULTn: J26.72 U30.6(1Y)
TTPLPFC_GAN_FAULT_PH1_H: U30.4(1C)
TTPLPFC_GAN_FAULT_PH1_L: U30.5(1D)
TTPLPFC_GAN_FAULT_PH2_H: U30.1(1A)
TTPLPFC_GAN_FAULT_PH2_L: U30.2(1B)
TTPLPFC_GAN_OC_HIGH_FREQ_PH1_H: R93.2
TTPLPFC_GAN_OC_HIGH_FREQ_PH1_L: R92.2
TTPLPFC_GAN_OC_HIGH_FREQ_PH2_H: J26.71
TTPLPFC_GAN_OC_HIGH_FREQ_PH2_L: J26.73
TTPLPFC_HIGH_FREQ_PH1_H: J26.61
TTPLPFC_HIGH_FREQ_PH1_L: J26.63
TTPLPFC_HIGH_FREQ_PH2_H: J26.58
TTPLPFC_HIGH_FREQ_PH2_L: J26.60
TTPLPFC_IAC_PH1: J26.15
TTPLPFC_IAC_PH2: J26.18
TTPLPFC_INRUSH_RELAY: J26.64
TTPLPFC_LOW_FREQ_H: J26.57
TTPLPFC_LOW_FREQ_L: J26.59
TTPLPFC_PH1_H_TEMP: U32.2(S1)
TTPLPFC_PH1_L_TEMP: U33.2(S1)
TTPLPFC_PH2_H_TEMP: U33.3(S2)
TTPLPFC_PH2_L_TEMP: U32.3(S2)
TTPLPFC_VAC: J26.39
TTPLPFC_VAC_L: J26.17
TTPLPFC_VAC_N: J26.14
TTPLPFC_VBUS: J26.20
TTPLPFC_VBUS2: C141.1 J26.25 R91.1 R94.2
XRSn: R89.2 U51.11(OUTE)
NetC138_2: C138.2 R86.2 R87.1
NetJ25_178: J25.178 R84.1
NetJ26_88: J26.88 R93.1
NetJ26_90: J26.90 R92.1
NetJ26_102: J26.102 R90.1
NetJ26_120: J26.120 R89.1
NetL11_1: L11.1 R85.1 U29.7(CANH)
NetL11_2: L11.2 R88.1 U29.6(CANL)
NetR94_1: R94.1 R95.2
NetR95_1: R95.1 R96.2
NetU30_9: U30.9(2A) U31.3(1Y)
NetU30_10: U30.10(2B) U31.6(2Y)
NetU30_12: U30.12(2C) U31.8(3Y)
NetU30_13: U30.13(2D) U31.11(4Y)

Not connected (* = marked no-connect by the designer): J24 11*; J25 121* 122* 123* 124* 125* 126* 127* 128* 129* 130* 131* 132* 133* 134* 136* 137* 138* 139* 140* 141* 142* 143* 144* 145* 146* 147* 148* 149* 150* 151* 152* 153* 154* 155* 156* 159* 160* 161* 162* 163* 164* 165* 166* 167* 168* 169* 170* 171* 172* 173* 174* 175* 176* 177*; J26 1* 2* 11* 12* 16* 23* 24* 30* 32* 40* 41* 42* 43* 44* 45* 46* 66* 76* 78* 79* 81* 82* 86* 89* 92* 113* 114* 115* 116* 117*; U30 3(NC)* 11(NC)*; U32 1(NC)* 7(S8)* 8(S7)*; U33 1(NC)* 7(S8)* 8(S7)*

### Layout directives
mark named HV: NetR95_1

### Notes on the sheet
- Notes:
- (near J26) 1. C2000 connector pin definition is different from Samtec definition.
- (near R89) ETAS Interface

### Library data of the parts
C138 = CMP-0007088-4: CAP, CERM, 4700 pF, 100 V, +/- 10%, X7R, AEC-Q200 Grade 1, 0603; Manufacturer: TDK; TaMin_C: -55°C; ESR_ohm: 4.69862d; Polarized: N; SizeAreaWB_mm2: 4.68; Value1: 0.469862 ohm; U/M: EA; Value: 4700pF; TaMax_C: 125°C; SizeZ_mm: 1; SizeX_mm: 1.6; SizeY_mm: 0.8; SizeArea_mm2: 1.28; AEC Qualified: Y; Cap_F: 4.7nF; IRMS_A: 3.2335dA; AEC Category: Q200
C139 C140 C142-C145 C251-C254 = CMP-0080610-1: CAP, CERM, 0.1 µF, 25 V,+/- 10%, X7R, AEC-Q200 Grade 1, 0402; Manufacturer: TDK; TaMin_C: -55°C; Polarized: N; SizeAreaWB_mm2: 3; U/M: EA; Value: 0.1uF; TaMax_C: 125°C; SizeZ_mm: 0.6; SizeX_mm: 1; SizeY_mm: 0.5; AEC Qualified: Y; Cap_F: 100nF; AEC Category: Q200
C141 = CMP-0007127-4: CAP, CERM, 470 pF, 50 V, +/- 5%, C0G/NP0, AEC-Q200 Grade 1, 0603; Manufacturer: MuRata; TaMin_C: -55°C; Polarized: N; SizeAreaWB_mm2: 4.68; Value1: Unknown; U/M: EA; Value: 470pF; TaMax_C: 125°C; SizeZ_mm: 1; SizeX_mm: 1.6; SizeY_mm: 0.8; SizeArea_mm2: 1.28; AEC Qualified: Y; AEC Category: Q200
D1 = CMP-0005919-3: Diode, TVS, Bi, 24 V, SOT-23; Manufacturer: ON Semiconductor; SizeAreaWB_mm2: 14; Value1: 350W; SizeZ_mm: 1.1; SizeX_mm: 2.5; SizeY_mm: 3; SizeArea_mm2: 7.5; AEC Category: Q101
J24 = CMP-0075601-2: Header(Shrouded), 1.27mm, 6x2, Tin, SMT; Manufacturer: Samtec; Pitch_mm: 1.27; Gender: Male; Cert_CSA: Y; Current_A: 3.2A; Voltage_V: 250V; ContactFinish: Gold; Row_Count: 2
J25 = CMP-0003859-2: C2000 controlCARD-180HSEC (60-pin addon) connector, SMT; Manufacturer: Samtec; Note: The pin numbering does not match Samtec datasheet
J26 = CMP-0003814-2: C2000 controlCARD-120HSEC connector, SMT; Manufacturer: Samtec; Note: The pin numbering does not match Samtec datasheet
L11 = CMP-0062430-2: Inductor, Ferrite, 100 uH, 0.15 A, 2 ohm, SMD; Manufacturer: TDK; Isat: 0.15A @ % inductance drop; Green_Lifecycle: Active; SizeAreaWB_mm2: 23.1; DCR_ohm: 2; Green_REACh: Passed; Value1: 2 ohm; Value: 100uH; Imax_A: 1.5dA; SizeZ_mm: 3; SizeX_mm: 4.5; SizeY_mm: 3.2; Value2: 0.15A; SizeArea_mm2: 14.4; Ind_H: 100µH; AEC Category: Q200
R84 R89 R90 R92 R93 = CMP-0025874-4: RES, 0, 5%, 0.1 W, AEC-Q200 Grade 0, 0603; Manufacturer: Panasonic; Power_W: 100mW; TempCo: 600 ppm/C; Value_Code: 0000; Value: 0; EIA_Code: E24; SizeX_mm: 1.6; SizeY_mm: 0.8; SizeZ_mm: 1; Value2: 0.1W; SizeArea_mm2: 1.28; AEC Qualified: Y; VDC_V: 50V; AEC Category: Q200; SizeAreaWB_mm2: 4.68
R85 R88 = CMP-0023343-3: RES, 0, 1%, 0.1 W, AEC-Q200 Grade 0, 0603; Manufacturer: Stackpole Electronics Inc; Power_W: 100mW; TempCo: ppm/C; U/M: EA; Value: 0; SizeX_mm: 1.6; SizeY_mm: 0.8; SizeZ_mm: 1; Value2: 0.1W; SizeArea_mm2: 1.28; AEC Qualified: Y; AEC Category: Q200
R86 R87 = CMP-0022532-4: RES, 60.4 k, 1%, 0.1 W, AEC-Q200 Grade 0, 0603; Manufacturer: Vishay-Dale; Power_W: 100mW; TempCo: 100 ppm/C; Value_Code: 60k4; Value: 60.4k; EIA_Code: E96; SizeX_mm: 1.6; SizeY_mm: 0.8; SizeZ_mm: 1; Value2: 0.1W; SizeArea_mm2: 1.28; AEC Qualified: Y; VDC_V: 75V; AEC Category: Q200; AEC Grade: 0
R91 = CMP-0022599-4: RES, 7.15 k, 1%, 0.1 W, AEC-Q200 Grade 0, 0603; Manufacturer: Vishay-Dale; Power_W: 100mW; TempCo: 100 ppm/C; Value_Code: 7k15; Value: 7.15k; EIA_Code: E96; SizeX_mm: 1.6; SizeY_mm: 0.8; SizeZ_mm: 1; Value2: 0.1W; SizeArea_mm2: 1.28; AEC Qualified: Y; VDC_V: 75V; AEC Category: Q200; AEC Grade: 0
R94-R96 = CMP-0016927-3: RES, 365 k, 1%, 0.25 W, AEC-Q200 Grade 0, 1206; Manufacturer: Vishay-Dale; Power_W: 250mW; TempCo: 100 ppm/C; Value: 365k; EIA_Code: E96; SizeX_mm: 3.2; SizeY_mm: 1.6; SizeZ_mm: 1.35; Value2: 0.25W; SizeArea_mm2: 5.12; AEC Qualified: Y; VDC_V: 200V; AEC Category: Q200; AEC Grade: 0
U28 = CMP-0054569-1: Header, 50mil, 4x1, Gold, TH; Manufacturer: Sullins Connector Solutions; CNHeader: TRUE; Green_Lifecycle: Not Set; Green_REACh: Incomplete; CT: FALSE
U29 = CMP-0090614-1: Isolated CAN Transceiver with 70V Bus Fault Protection and Flexible Data Rate 8-Pin SOIC T/R; Manufacturer: Texas Instruments; SizeZ_mm: 2.8mm; AEC Qualified: Yes; Standoff Height: 0.36mm; AEC Grade: Grade 1; TaMax_C: +125°C; Nominal Supply Current: 1.2-43mA; Max Supply Voltage: 5.5V; TJmax_C: +150°C; Min Supply Voltage: 1.71V; TaMin_C: -40°C
U30 = CMP-0054468-2: Automotive Catalog Dual 4-Input Positive-AND Gates, PW0014A, LARGE T&R; Generic Part Number: SN74HC21-Q1; Manufacturer: Texas Instruments; Output Type: CMOS; VCC(Min)(V): 2; Voltage(Nom)(V): 5; F @ Nom Voltage(Max)(Mhz): 70; tpd @ Nom Voltage(Max)(ns): 140; Output Drive (IOL/IOH)(Max)(mA): -5.2/5.2; VCC(Max)(V): 6; Schmitt Trigger: No; Technology Family: HC; ICC @ Nom Voltage(Max)(mA): 0.02; AEC Category: Q200; CompType: IC
U31 = CMP-0054514-2: Automotive Catalog Quadruple 2-Input Positive-AND Gates, PW0014A, LARGE T&R; Generic Part Number: SN74AHCT08Q-Q1; Manufacturer: Texas Instruments; Voltage(Nom)(V): 5; VCC(Min)(V): 4.5; VCC(Max)(V): 5.5; ICC @ Nom Voltage(Max)(mA): 0.02; Bits(#): 4; Output Type: CMOS; F @ Nom Voltage(Max)(Mhz): 70; Technology Family: AHCT; Schmitt Trigger: No; tpd @ Nom Voltage(Max)(ns): 9; Input Type: TTL; Output Drive (IOL/IOH)(Max)(mA): -8/8; AEC Category: Q200; CompType: IC
U32 U33 = CMP-0090592-1: Automotive, 5-V bidirectional 8:1 multiplexer with 1.8-V logic; Manufacturer: Texas Instruments; TaMax_C: +125°C; Max Supply Voltage: 5.5V; AEC Qualified: Yes; PositionCount: 1; Min Supply Voltage: 1.08V; Nominal Supply Current: 0.02uA; Standoff Height: 0mm; -3Db Bandwith: 65MHz; TaMin_C: -40°C; SizeZ_mm: 0.55mm; TJmax_C: +150°C; AEC Grade: Grade 1; On State Resistance: 5Ω
U51 = CMP-0078425-1: High Speed, Robust EMC, Reinforced Six-Channel Digital Isolator, DBQ0016A (SSOP-16); Alternate Manufacturer: Texas Instruments; SizeAreaWB_mm2: 96; SizeZ_mm: 1.75; SizeX_mm: 6; SizeY_mm: 10; SizeArea_mm2: 60; CompType: IC; AEC Qualified: N; AEC Category: Q200
U52 = CMP-0013038-3: High Speed, Robust EMC Reinforced Triple-Channel Digital Isolator, DBQ0016A (SSOP-16); Manufacturer: Texas Instruments; SizeX_mm: 6; SizeY_mm: 10; CompType: IC; SizeZ_mm: 1.75; SizeArea_mm2: 60; SizeAreaWB_mm2: 96; AEC Category: Q200; AEC Qualified: N

## Sheet PMP22650 Bias Power and Monitors.SchDoc
size 431 x 279 mm; Date: Not shown in title block; ApprovedBy: Not shown in title block; CheckedBy: Not shown in title block; Author: Not shown in title block; CompanyName: Not shown in title block; Engineer: Not shown in title block; Organization: Not shown in title block; Address1: Not shown in title block; Address2: Not shown in title block; Address3: Not shown in title block; Address4: Not shown in title block; DocumentNumber: 9; Revision: Use project parameter SCH_Rev; SheetNumber: 9; SheetTotal: 16; PageSetup: Record=PageOptions¦CenterHorizontal=True¦CenterVertical=True¦PrintScale=1.00¦XCorrection=1.00¦YCorrection=1.00¦PrintKind=0¦BorderSize=5000000¦LeftOffset=0¦BottomOffset=0¦Orientation=2¦PaperLength=1000¦PaperWidth=1000¦Scale=100¦PaperSource=15¦PrintQuality=600¦MediaType=1¦DitherType=10¦PaperKind=Letter¦PrintScaleMode=1
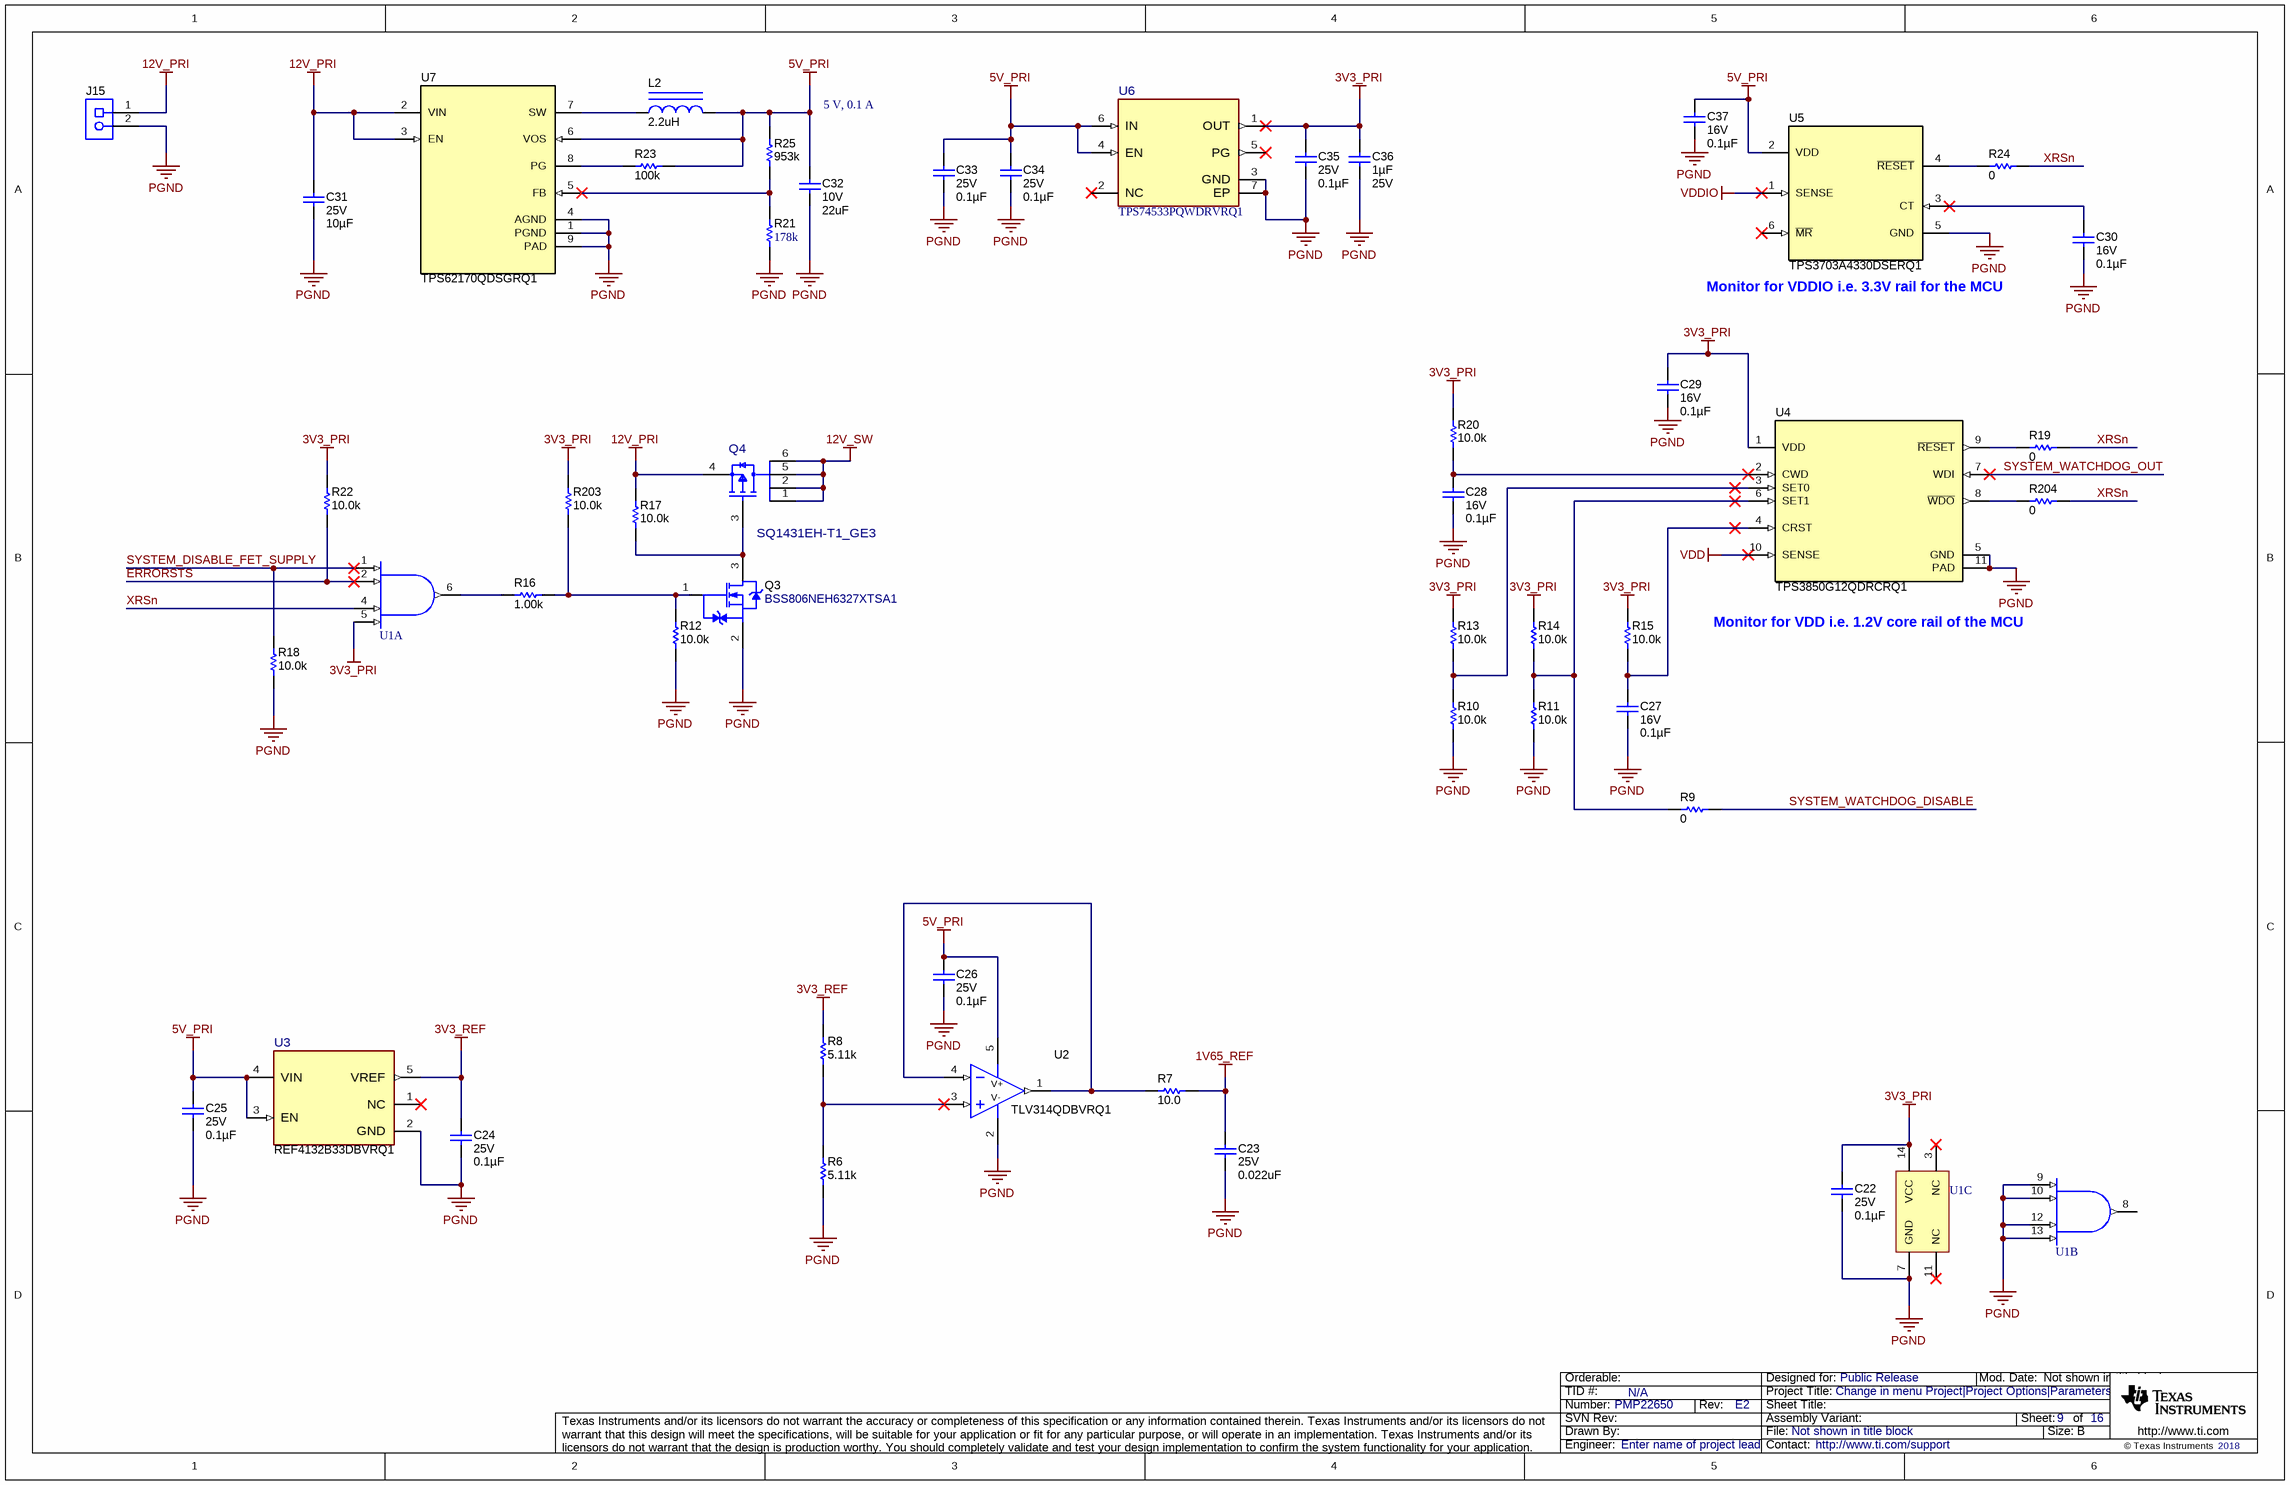
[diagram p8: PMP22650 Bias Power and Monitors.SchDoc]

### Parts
C22  VDC_V: 25V  ValueDisplayed: 0.1µF  [0402]  (hidden comment: CGA2B3X7R1E104K050BB)
C23  VDC_V: 25V  ValueDisplayed: 0.022uF  [0402]  (hidden comment: GCM155R71E223KA55D)
C24  VDC_V: 25V  ValueDisplayed: 0.1µF  [0402]  (hidden comment: CGA2B3X7R1E104K050BB)
C25  VDC_V: 25V  ValueDisplayed: 0.1µF  [0402]  (hidden comment: CGA2B3X7R1E104K050BB)
C26  VDC_V: 25V  ValueDisplayed: 0.1µF  [0402]  (hidden comment: CGA2B3X7R1E104K050BB)
C27  VDC_V: 16V  ValueDisplayed: 0.1µF  [0402]  (hidden comment: GCM155R71C104JA55D)
C28  VDC_V: 16V  ValueDisplayed: 0.1µF  [0402]  (hidden comment: GCM155R71C104JA55D)
C29  VDC_V: 16V  ValueDisplayed: 0.1µF  [0402]  (hidden comment: GCM155R71C104JA55D)
C30  VDC_V: 16V  ValueDisplayed: 0.1µF  [0402]  (hidden comment: GCM155R71C104JA55D)
C31  VDC_V: 25V  ValueDisplayed: 10µF  [1206_180]  (hidden comment: C1206C106J3RACAUTO)
C32  VDC_V: 10V  ValueDisplayed: 22uF  [1206_180]  (hidden comment: GRT31CC81A226KE01L)
C33  VDC_V: 25V  ValueDisplayed: 0.1µF  [0402]  (hidden comment: CGA2B3X7R1E104K050BB)
C34  VDC_V: 25V  ValueDisplayed: 0.1µF  [0402]  (hidden comment: CGA2B3X7R1E104K050BB)
C35  VDC_V: 25V  ValueDisplayed: 0.1µF  [0402]  (hidden comment: CGA2B3X7R1E104K050BB)
C36  Cap_F: 1µF  VDC_V: 25V  [0603]  (hidden comment: CGA3E1X7R1E105K080AD)
C37  VDC_V: 16V  ValueDisplayed: 0.1µF  [0402]  (hidden comment: GCM155R71C104JA55D)
J15  282856-2  [TE_282856-2]  (value not drawn)
L2  ValueDisplayed: 2.2uH  [SRN3015TA]  (hidden comment: SRN3015TA-2R2M)
Q3  BSS806NEH6327XTSA1  [SOT-23L]
Q4  SQ1431EH-T1_GE3  [FP-SQ1431EH-T1_GE3_SC-70-MFG]
R6  ValueDisplayed: 5.11k  [0402]  (hidden comment: CRCW04025K11FKED)
R7  ValueDisplayed: 10.0  [0402]  (hidden comment: RMCF0402JT10R0)
R8  ValueDisplayed: 5.11k  [0402]  (hidden comment: CRCW04025K11FKED)
R9  ValueDisplayed: 0  [0402]  (hidden comment: ERJ-2GE0R00X)
R10  ValueDisplayed: 10.0k  [0402]  (hidden comment: ERJPA2F1002X)
R11  ValueDisplayed: 10.0k  [0402]  (hidden comment: ERJPA2F1002X)
R12  ValueDisplayed: 10.0k  [0402]  (hidden comment: ERJPA2F1002X)
R13  ValueDisplayed: 10.0k  [0402]  (hidden comment: ERJPA2F1002X)
R14  ValueDisplayed: 10.0k  [0402]  (hidden comment: ERJPA2F1002X)
R15  ValueDisplayed: 10.0k  [0402]  (hidden comment: ERJPA2F1002X)
R16  ValueDisplayed: 1.00k  [0402]  (hidden comment: CRCW04021K00FKED)
R17  ValueDisplayed: 10.0k  [0402]  (hidden comment: ERJPA2F1002X)
R18  ValueDisplayed: 10.0k  [0402]  (hidden comment: ERJPA2F1002X)
R19  ValueDisplayed: 0  [0402]  (hidden comment: ERJ-2GE0R00X)
R20  ValueDisplayed: 10.0k  [0402]  (hidden comment: ERJPA2F1002X)
R21  ValueDisplayed: 178k  [0402]  (hidden comment: CRCW0402178KFKED)
R22  ValueDisplayed: 10.0k  [0402]  (hidden comment: ERJPA2F1002X)
R23  ValueDisplayed: 100k  [0402]  (hidden comment: CRCW0402100KDHEDP)
R24  ValueDisplayed: 0  [0402]  (hidden comment: ERJ-2GE0R00X)
R25  ValueDisplayed: 953k  [0402]  (hidden comment: CRCW0402953KFKED)
R203  ValueDisplayed: 10.0k  [0402]  (hidden comment: ERJPA2F1002X)
R204  ValueDisplayed: 0  [0402]  (hidden comment: ERJ-2GE0R00X)
U1  SN74HC21QPWRG4Q1  [PW0014A_N]  (value not drawn)  (parts A,B,C of 3)
U2  TLV314QDBVRQ1  [DBV0005A_N]
U3  REF4132B33DBVRQ1  [DBV0005A-MFG]
U4  TPS3850G12QDRCRQ1  [DRC0010R]
U5  TPS3703A4330DSERQ1  [DSE0006A]
U6  TPS74533PQWDRVRQ1  [DRV0006C-MFG]
U7  TPS62170QDSGRQ1  [DSG0008A]

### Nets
1V65_REF: C23.1 R7.2
3V3_PRI: C22.1 C29.1 C35.2 C36.1 R13.2 R14.2 R15.2 R20.2 R22.2 R203.2 U1.5(1D) U1.14(VCC) U4.1(VDD) U6.1(OUT)
3V3_REF: C24.2 R8.2 U3.5(VREF)
5V_PRI: C25.2 C26.2 C32.1 C33.2 C34.2 C37.1 L2.2 R23.2 R25.2 U2.5(V+) U3.3(EN) U3.4(VIN) U5.2(VDD) U6.4(EN) U6.6(IN) U7.6(VOS)
12V_PRI: C31.1 J15.1 Q4.4(S) R17.2 U7.2(VIN) U7.3(EN)
12V_SW: Q4.1(D) Q4.2(D) Q4.5(D) Q4.6(D)
PGND: C22.2 C23.2 C24.1 C25.1 C26.1 C27.2 C28.2 C29.2 C30.2 C31.2 C32.2 C33.1 C34.1 C35.1 C36.2 C37.2 J15.2 Q3.2(S) R6.1 R10.1 R11.1 R12.1 R18.1 R21.1 U1.7(GND) U1.9(2A) U1.10(2B) U1.12(2C) U1.13(2D) U2.2(V-) U3.2(GND) U4.5(GND) U4.11(PAD) U5.5(GND) U6.3(GND) U6.7(EP) U7.1(PGND) U7.4(AGND) U7.9(PAD)
VDD: U4.10(SENSE)
VDDIO: U5.1(SENSE)
ERRORSTS: R22.1 U1.2(1B)
SYSTEM_DISABLE_FET_SUPPLY: R18.2 U1.1(1A)
SYSTEM_WATCHDOG_DISABLE: R9.2
SYSTEM_WATCHDOG_OUT: U4.7(WDI)
XRSn: R19.2 R24.2 R204.2 U1.4(1C)
NetC27_1: C27.1 R15.1 U4.4(CRST)
NetC28_1: C28.1 R20.1 U4.2(CWD)
NetC30_1: C30.1 U5.3(CT)
NetL2_1: L2.1 U7.7(SW)
NetQ3_1: Q3.1(G) R12.2 R16.2 R203.1
NetQ3_3: Q3.3(D) Q4.3(G) R17.1
NetR6_2: R6.2 R8.1 U2.3(IN+)
NetR7_1: R7.1 U2.1(OUT) U2.4(IN-)
NetR9_1: R9.1 R11.2 R14.1 U4.6(SET1)
NetR10_2: R10.2 R13.1 U4.3(SET0)
NetR16_1: R16.1 U1.6(1Y)
NetR19_1: R19.1 U4.9(~{RESET})
NetR21_2: R21.2 R25.1 U7.5(FB)
NetR23_1: R23.1 U7.8(PG)
NetR24_1: R24.1 U5.4(~{RESET})
NetR204_1: R204.1 U4.8(~{WDO})

Not connected (* = marked no-connect by the designer): U1 3(NC)* 8(2Y) 11(NC)*; U3 1(NC)*; U5 6(~{MR})*; U6 2(NC)* 5(PG)*

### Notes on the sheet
- 5 V, 0.1 A
- (near U5) Monitor for VDDIO i.e. 3.3V rail for the MCU
- (near U4) Monitor for VDD i.e. 1.2V core rail of the MCU

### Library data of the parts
C22 C24-C26 C33-C35 = CMP-0080610-1: as C139 on sheet PMP22650 Control
C23 = CMP-0006353-2: CAP, CERM, 0.022 uF, 25 V, +/- 10%, X7R, AEC-Q200 Grade 1, 0402; Manufacturer: MuRata; TaMin_C: -55°C; Polarized: N; SizeAreaWB_mm2: 3; Value1: Unknown; U/M: EA; TaMax_C: 125°C; SizeZ_mm: 0.6; SizeX_mm: 1; SizeY_mm: 0.5; AEC Qualified: Y; Cap_F: 22nF; AEC Category: Q200
C27-C30 C37 = CMP-0080702-1: CAP, CERM, 0.1 µF, 16 V,+/- 5%, X7R, AEC-Q200 Grade 1, 0402; Manufacturer: MuRata; Cap_F: 100nF; SizeAreaWB_mm2: 3; SizeArea_mm2: 0.5; AEC Qualified: Y; AEC Category: Q200; Value: 0.1uF; TaMax_C: 125°C; SizeZ_mm: 0.6; AEC Grade: 1; Polarized: N; TaMin_C: -55°C; U/M: EA
C31 = CMP-0081062-1: CAP, CERM, 10 µF, 25 V,+/- 5%, X7R, AEC-Q200 Grade 1, 1206; Manufacturer: Kemet; TaMin_C: -55°C; Polarized: N; SizeAreaWB_mm2: 10.92; U/M: EA; Value: 10uF; TaMax_C: 125°C; SizeZ_mm: 1.8; SizeX_mm: 3.2; SizeY_mm: 1.6; SizeArea_mm2: 5.12; AEC Qualified: Y; AEC Grade: 1; AEC Category: Q200
C32 = CMP-0009012-3: CAP, CERM, 22 uF, 10 V, +/- 10%, X6S, AEC-Q200 Grade 2, 1206; Manufacturer: MuRata; TaMin_C: -55°C; Polarized: N; SizeAreaWB_mm2: 10.92; Value1: Unknown; U/M: EA; Value: 22uF; TaMax_C: 105°C; SizeZ_mm: 1.8; SizeX_mm: 3.2; SizeY_mm: 1.6; Cap_Case: 1206; SizeArea_mm2: 5.12; AEC Qualified: Y; Cap_F: 22µF; AEC Grade: 2; AEC Category: Q200
C36 = CMP-0082523-1: CAP, CERM, 1 µF, 25 V,+/- 10%, X7R, AEC-Q200 Grade 1, 0603; Manufacturer: TDK; SizeAreaWB_mm2: 4.68; SizeArea_mm2: 1.28; AEC Qualified: Y; AEC Category: Q200; Value: 1uF; TaMax_C: 125°C; SizeZ_mm: 1; Polarized: N; TaMin_C: -55°C; SizeY_mm: 0.8; U/M: EA; SizeX_mm: 1.6
J15 = CMP-0054978-1: Therminal Block, 5 mm, 2-pole, Tin, TH; Manufacturer: On Shore Technology Inc.; PartNumber: ED700/2; CT: TRUE; CompType: Terminal Block; CNHeader: FALSE
L2 = CMP-0056750-1: Inductor, Shielded, Ferrite, 2.2 uH, 1.7 A, 0.072 ohm, AEC-Q200 Grade 1, SMD; Manufacturer: Bourns; Isat: 1.7A @ 30% inductance drop; Irms: 1.7A @ 40C rise; Green_Lifecycle: Active; SizeAreaWB_mm2: 16; DCR_ohm: 0.072; Green_REACh: Passed; Value: 2.2uH; Imax_A: 1.7A; SizeZ_mm: 1.5; SizeX_mm: 3; SizeArea_mm2: 9; Ind_H: 2.2µH; AEC Qualified: Y; AEC Grade: 1; AEC Category: Q200
Q3 = CMP-0077248-1: MOSFET, N-CH, 20 V, 2.3 A, AEC-Q101, SOT-23; Manufacturer: Infineon Technologies; Alternate Manufacturer: None; ChType: N; QgTyp_nC: 1.7; SizeAreaWB_mm2: 14.0; SizeArea_mm2: 7.5; IdsMax_A: 2.3A; AEC Qualified: Y; VdsMax_V: 20V; Vgs_V: 8V; AEC Category: Q101; Value: 20V; SizeZ_mm: 1.1; SizeY_mm: 3.0; Value2: 1.7 nC; U/M: EA; Value1: ? ohm; SizeX_mm: 2.5
Q4 = CMP-0090551-1: P-Channel 30V 3A (Tc) 3W (Tc) Surface Mount SC-70-6 (SOT-363); Manufacturer: Vishay; Turn Off Delay Time: 11ns; Threshold Vgs Max: -2V; Rthja Max: 130°C/W; Number Of Channels: 1; AEC Qualified: Yes; TJmax_C: +175°C; Vgs_V: 20V; Drain To Source Breakdown Voltage: -30V; Typ Forward Diode Voltage: -0.85V; AEC Grade: Grade 0; Threshold Vgs Min: -1V; Rdson45_ohm: 0.125; ChMode: False; Input Capacitace At Vds: 164pF @ -25V; Turn On Delay Time: 5ns; IdsMax_A: -3A; SizeZ_mm: 1.1mm; QgTyp_nC: 4.2nC @ -4.5V; Pulse Drain Current: -12A; VdsMax_V: -1.2V; Transconductance: 3S
R6 R8 = CMP-0026463-2: RES, 5.11 k, 1%, 0.063 W, AEC-Q200 Grade 0, 0402; Manufacturer: Vishay-Dale; Power_W: 63mW; TempCo: 100 ppm/C; Value_Code: 5k11; Value: 5.11k; EIA_Code: E96; SizeX_mm: 1; SizeY_mm: 0.5; SizeZ_mm: 0.6; Value2: 0.063W; AEC Qualified: Y; VDC_V: 50V; AEC Category: Q200; AEC Grade: 0
R7 = CMP-0026764-1: RES, 10.0, 1%, 0.063 W, AEC-Q200 Grade 0, 0402; Manufacturer: Stackpole Electronics Inc; Power_W: 63mW; TempCo: 100 ppm/C; Value_Code: 10R0; U/M: EA; Value: 10.0; EIA_Code: E96; Res_ohm: 10; SizeX_mm: 1; SizeY_mm: 0.5; SizeZ_mm: 0.6; Value2: 0.063W; AEC Qualified: Y; AEC Grade: 0; AEC Category: Q200
R9 R19 R24 R204 = CMP-0026992-3: as R108 on sheet PMP22650 PFC GaN PH2
R10-R15 R17 R18 R20 R22 R203 = CMP-0078779-1: RES, 10.0 k, 1%, 0.2 W, AEC-Q200 Grade 0, 0402; Manufacturer: Panasonic; Value_Code: 10k0; SizeArea_mm2: 0.5; AEC Qualified: Y; AEC Category: Q200; Res_ohm: 10k; Value: 10.0k; SizeZ_mm: 0.6; EIA_Code: E96; TempCo: 100 ppm/C; AEC Grade: 0; Power_W: 200mW; VDC_V: 50V; Value2: 0.2W; SizeX_mm: 1
R16 = CMP-0026071-3: RES, 1.00 k, 1%, 0.063 W, AEC-Q200 Grade 0, 0402; Manufacturer: Vishay-Dale; Power_W: 63mW; TempCo: 100 ppm/C; Value_Code: 1k00; Value: 1.00k; EIA_Code: E96; Res_ohm: 1k; SizeX_mm: 1; SizeY_mm: 0.5; SizeZ_mm: 0.6; Value2: 0.063W; AEC Qualified: Y; VDC_V: 50V; AEC Category: Q200; AEC Grade: 0
R21 = CMP-0026048-3: RES, 178 k, 1%, 0.063 W, AEC-Q200 Grade 0, 0402; Manufacturer: Vishay-Dale; Power_W: 63mW; TempCo: 100 ppm/C; Value: 178k; EIA_Code: E96; SizeX_mm: 1; SizeY_mm: 0.5; SizeZ_mm: 0.6; Value2: 0.063W; AEC Qualified: Y; VDC_V: 50V; AEC Category: Q200; AEC Grade: 0
R23 = CMP-0026768-2: RES, 100 k, 0.5%, 0.063 W, AEC-Q200 Grade 0, 0402; Manufacturer: Vishay-Dale; Power_W: 63mW; TempCo: 50 ppm/C; Value: 100k; EIA_Code: E192; SizeX_mm: 1; SizeY_mm: 0.5; SizeZ_mm: 0.6; Value2: 0.063W; AEC Qualified: Y; VDC_V: 50V; AEC Category: Q200; AEC Grade: 0
R25 = CMP-0026611-3: RES, 953 k, 1%, 0.063 W, AEC-Q200 Grade 0, 0402; Manufacturer: Vishay-Dale; Power_W: 63mW; TempCo: 100 ppm/C; Value: 953k; EIA_Code: E96; SizeX_mm: 1; SizeY_mm: 0.5; SizeZ_mm: 0.6; Value2: 0.063W; AEC Qualified: Y; VDC_V: 50V; AEC Category: Q200; AEC Grade: 0
U1 = CMP-0054468-2: as U30 on sheet PMP22650 Control
U2 = CMP-0073534-1: 3-MHz, Low-Power, Internal EMI Filter, RRIO, Operational Amplifier, DBV0005A (SOT-23-5); Alternate PartNumber: TLV314QDBVTQ1; Alternate Manufacturer: Texas Instruments; SizeAreaWB_mm2: 14.82; U/M: EA; SizeZ_mm: 1.45; SizeX_mm: 2.8; SizeY_mm: 2.9; SizeArea_mm2: 8.12; CompType: IC
U3 = CMP-0090523-1: Voltage References Automotive 12-ppm/ C low-noise low-power precision voltage reference; Manufacturer: Texas Instruments; Min Supply Voltage: 2.8V; Nominal Supply Current: 80uA; TaMax_C: +125°C; Max Supply Voltage: 5.5V; Reference Type: Series; Output Type: Fixed; Number Of Outputs: 1; Standoff Height: 0mm; Output Voltage: 3.3V; TaMin_C: -40°C; SizeZ_mm: 1.45mm; AEC Qualified: Yes; AEC Grade: Grade 1
U4 = CMP-0081428-2: Automotive Precision Voltage Supervisor With Programmable Window Watchdog Timer, DRC0010R (VSON-10); Alternate Manufacturer: Texas Instruments; SizeAreaWB_mm2: 16; SizeZ_mm: 1; SizeX_mm: 3; SizeArea_mm2: 9; CompType: IC; AEC Qualified: Y; AEC Category: Q200
U5 = CMP-0750051-1: Overvoltage and Undervoltage Reset IC With Time Delay and Manual Reset, DSE0006A (WSON-6); Alternate Manufacturer: Texas Instruments; AEC Category: Q200; SizeY_mm: 1.5; AEC Qualified: Y; SizeAreaWB_mm2: 6.25; SizeZ_mm: 0.8; SizeArea_mm2: 2.25
U6 = CMP-0090683-1: Linear Voltage Regulator IC  1 Output  500mA 6-WSON (2x2); Manufacturer: Texas Instruments; TaMax_C: +125°C; Max Supply Voltage: 6V; Min Supply Voltage: 4.15V; AEC Grade: Grade 1; Nominal Supply Current: 25uA; Dropout Voltage: 95mV; Number Of Outputs: 1; Accuracy Percentage: 0.85%; Standoff Height: 0mm; Output Type: Fixed; TaMin_C: -40°C; SizeZ_mm: 0.8mm; Output Voltage: 3.3V; TJmax_C: +150°C; AEC Qualified: Yes
U7 = CMP-0067104-2: 3-17V 0.5A Automotive Step-Down Converter in 2x2 QFN package, DSG0008A (WSON-8); Alternate PartNumber: TPS62170QDSGTQ1; Manufacturer: Texas Instruments; SizeZ_mm: 0.8; SizeX_mm: 2.0; SizeArea_mm2: 4.0; CompType: IC; U/M: EA; SizeAreaWB_mm2: 9.0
